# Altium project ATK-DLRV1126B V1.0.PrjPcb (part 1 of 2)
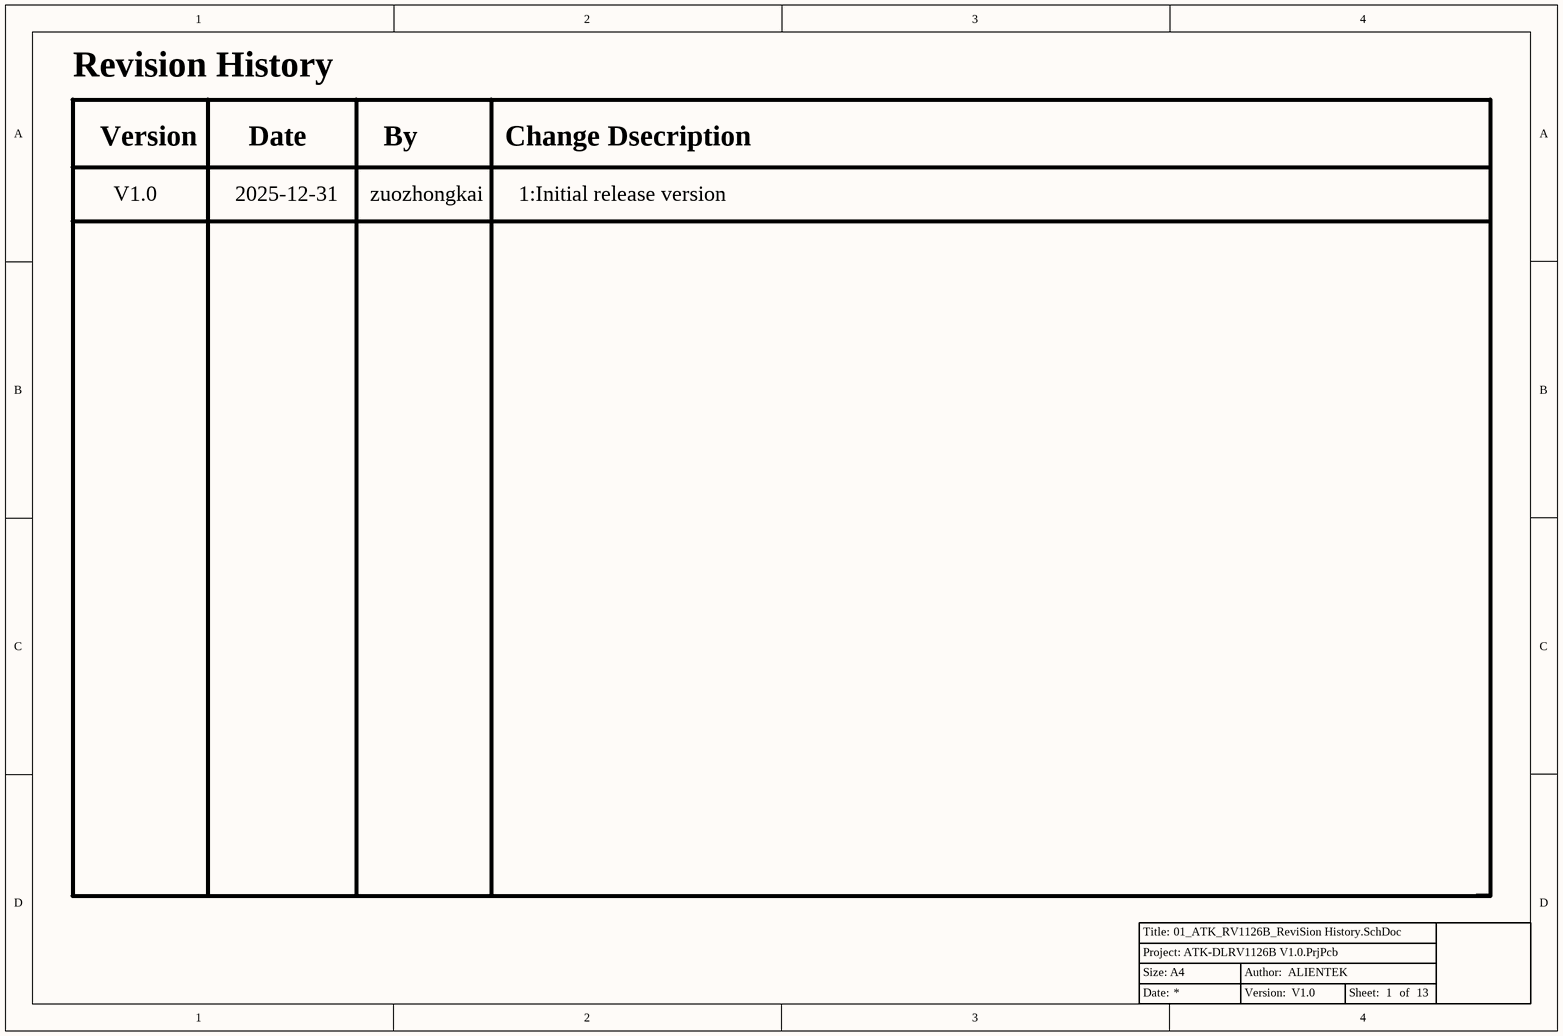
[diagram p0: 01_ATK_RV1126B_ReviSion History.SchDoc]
13 sheets, 503 parts. Net scope: global (net labels, ports and power ports of the same name join across sheets).
Sheets:
  01_ATK_RV1126B_ReviSion History.SchDoc
  02_ATK_RV1126B_Core_Board.SchDoc
  03_ATK_RV1126B_Power_USB.SchDoc
  04_ATK_RV1126B_4G_USBHUB.SchDoc
  05_ATK_RV1126B_DEVICE.SchDoc
  06_ATK_RV1126B_ES8390_Audio.SchDoc
  07_ATK_RV1126B_Integrate_Audio_OPT.SchDoc
  08_ATK_RV1126B_RS485_CAN.SchDoc
  09_ATK_RV1126B_RGMII_NET.SchDoc
  10_ATK_RV1126B_FEPHY_NET_OPT.SchDoc
  11_ATK_RV1126B_TYPEC_USB30.SchDoc
  12_ATK_RV1126B_CSI_DSI.SchDoc
  13_ATK_RV1126B_WIFI_CIF_PIN.SchDoc

## Sheet 01_ATK_RV1126B_ReviSion History.SchDoc
size A4; Author: ALIENTEK; SheetNumber: 1; SheetTotal: 13; SheetSize: A4; Version: V1.0

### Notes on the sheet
- Revision History
- Version
- Date
- By
- Change Dsecription
- V1.0
- 2025-12-31
- zuozhongkai
- 1:Initial release version

## Sheet 02_ATK_RV1126B_Core_Board.SchDoc
size A3; Date: 13; Author: ALIENTEK; Revision: 0; SheetNumber: 2; SheetTotal: 13; Version: V1.0; SheetSize: A3
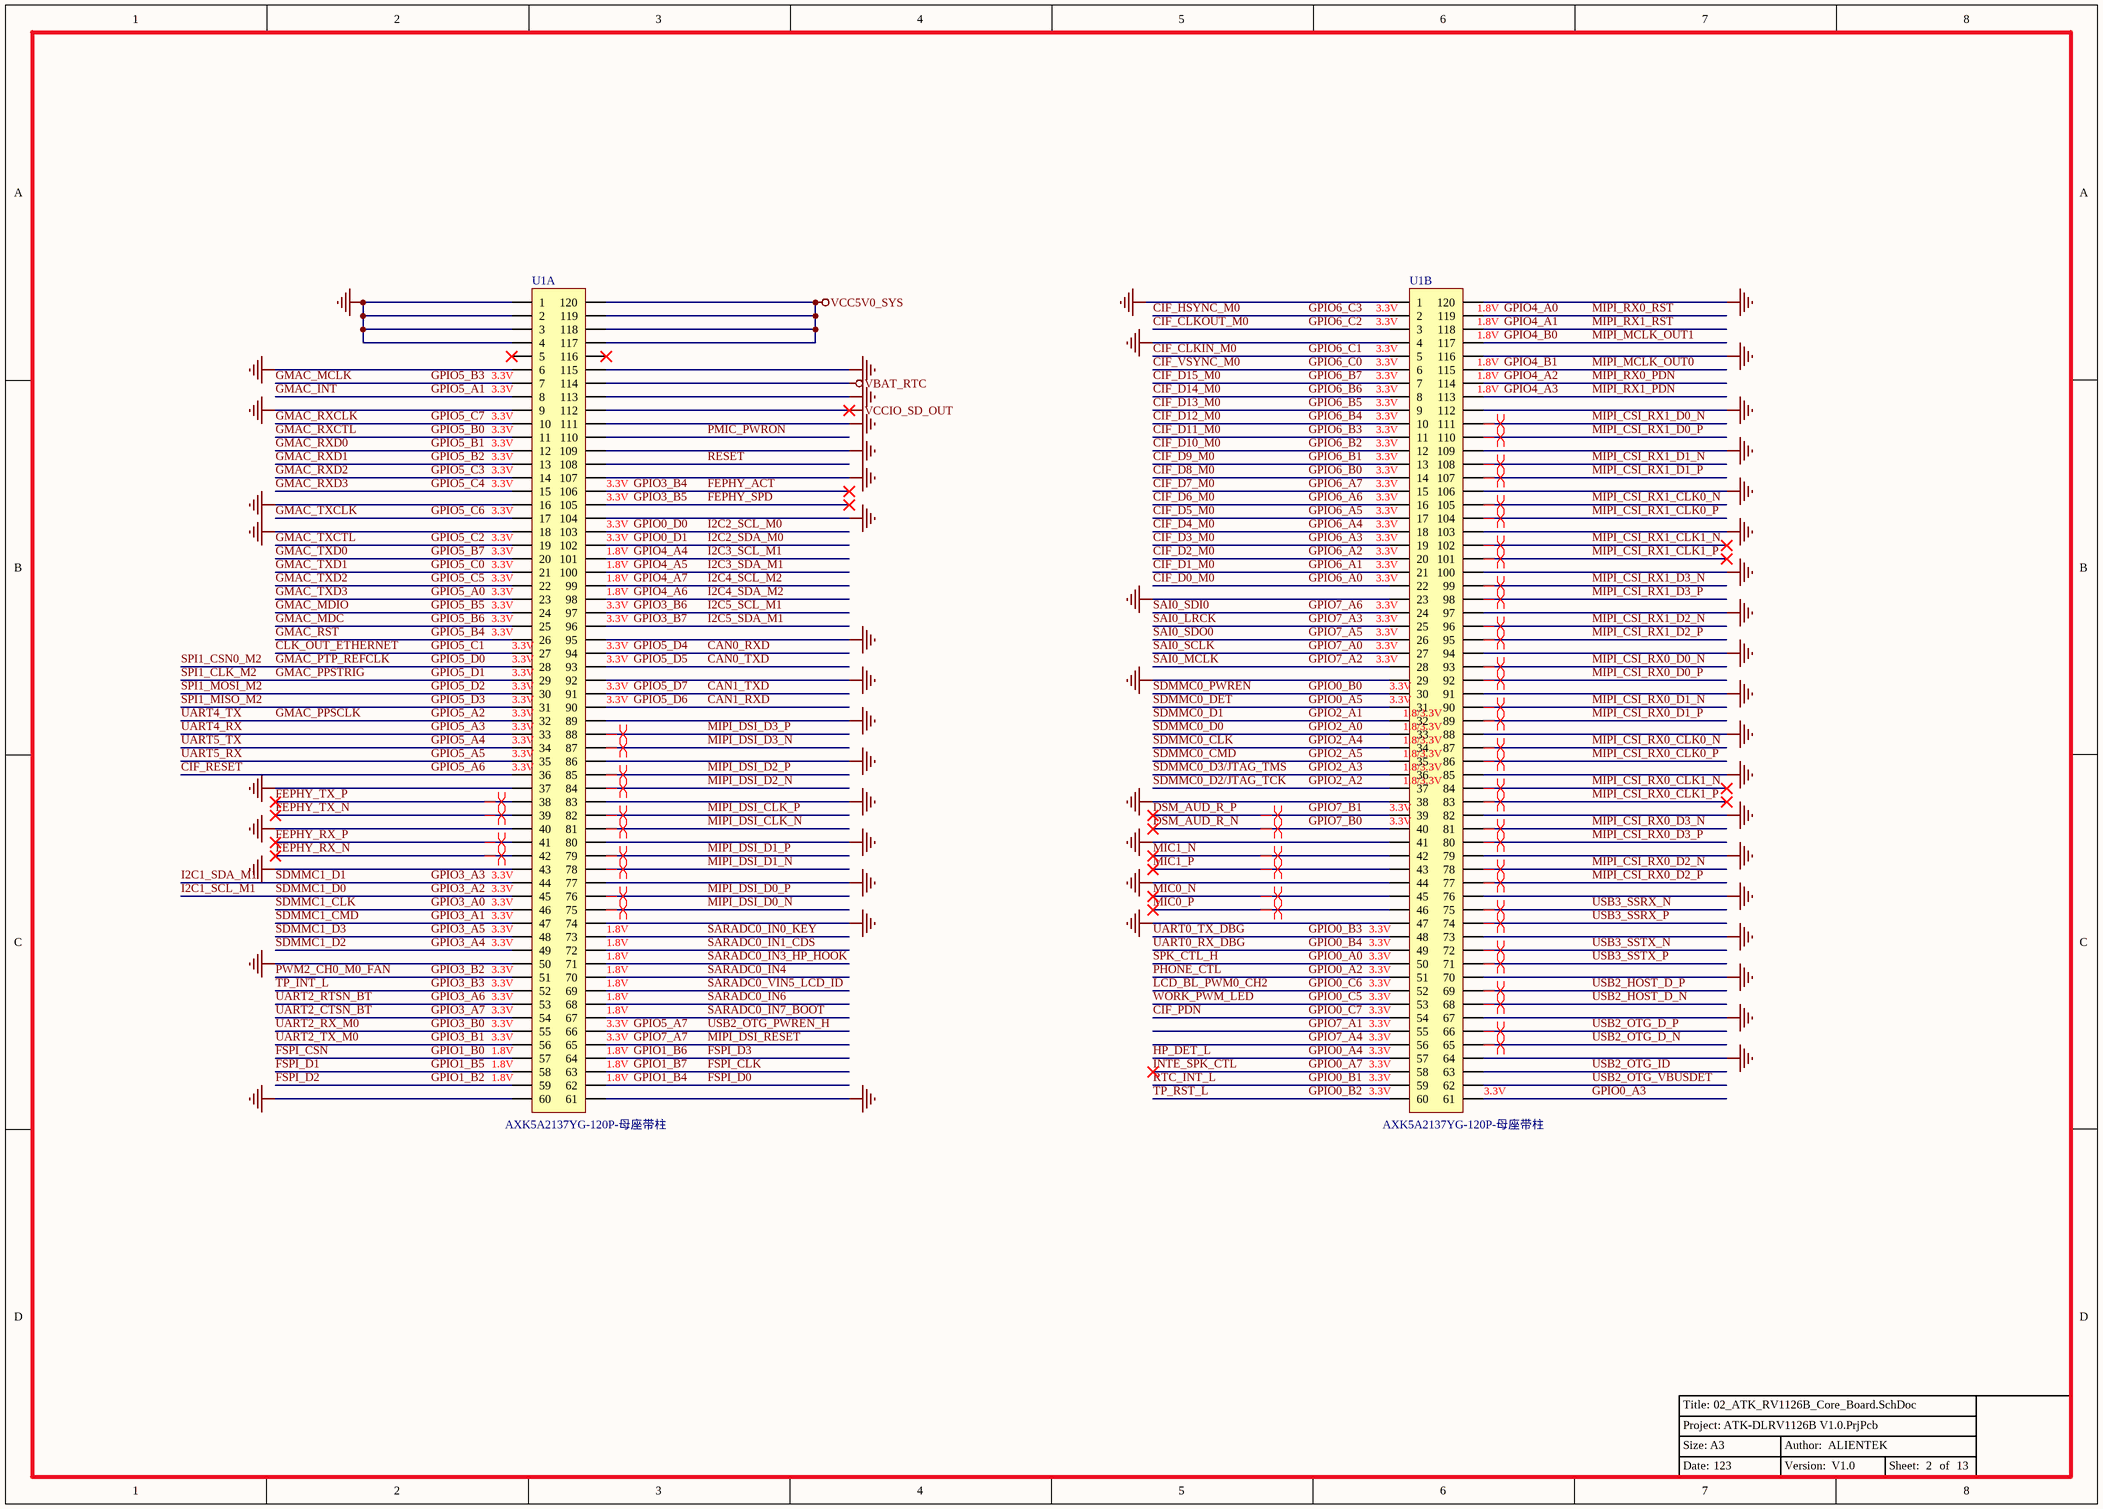
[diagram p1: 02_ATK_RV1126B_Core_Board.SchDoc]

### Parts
U1  AXK5A2137YG-120P-母座带柱  [ATK-CLRV1126B-CORE]  (parts A,B of 2)

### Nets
GND: U1.A1(1) U1.A2(2) U1.A3(3) U1.A4(4) U1.A6(6) U1.A9(9) U1.A16(16) U1.A18(18) U1.A37(37) U1.A40(40) U1.A43(43) U1.A50(50) U1.A60(60) U1.A61(61) U1.A74(74) U1.A77(77) U1.A80(80) U1.A83(83) U1.A86(86) U1.A89(89) U1.A92(92) U1.A95(95) U1.A104(104) U1.A107(107) U1.A109(109) U1.A111(111) U1.A113(113) U1.A115(115) U1.B1(1) U1.B4(4) U1.B23(23) U1.B29(29) U1.B38(38) U1.B41(41) U1.B44(44) U1.B47(47) U1.B64(64) U1.B67(67) U1.B70(70) U1.B73(73) U1.B76(76) U1.B79(79) U1.B82(82) U1.B85(85) U1.B88(88) U1.B91(91) U1.B94(94) U1.B97(97) U1.B100(100) U1.B103(103) U1.B106(106) U1.B109(109) U1.B112(112) U1.B116(116) U1.B120(120)
VBAT_RTC: U1.A114(114)
VCC5V0_SYS: U1.A117(117) U1.A118(118) U1.A119(119) U1.A120(120)
VCCIO_SD_OUT: U1.A112(112)
CAN0_RXD: U1.A94(94)  [also labelled GPIO5_D4]
CAN0_TXD: U1.A93(93)  [also labelled GPIO5_D5]
CAN1_RXD: U1.A90(90)  [also labelled GPIO5_D6]
CAN1_TXD: U1.A91(91)  [also labelled GPIO5_D7]
CIF_CLKIN_M0: U1.B5(5)  [also labelled GPIO6_C1]
CIF_CLKOUT_M0: U1.B3(3)  [also labelled GPIO6_C2]
CIF_D0_M0: U1.B22(22)  [also labelled GPIO6_A0]
CIF_D1_M0: U1.B21(21)  [also labelled GPIO6_A1]
CIF_D2_M0: U1.B20(20)  [also labelled GPIO6_A2]
CIF_D3_M0: U1.B19(19)  [also labelled GPIO6_A3]
CIF_D4_M0: U1.B18(18)  [also labelled GPIO6_A4]
CIF_D5_M0: U1.B17(17)  [also labelled GPIO6_A5]
CIF_D6_M0: U1.B16(16)  [also labelled GPIO6_A6]
CIF_D7_M0: U1.B15(15)  [also labelled GPIO6_A7]
CIF_D8_M0: U1.B14(14)  [also labelled GPIO6_B0]
CIF_D9_M0: U1.B13(13)  [also labelled GPIO6_B1]
CIF_D10_M0: U1.B12(12)  [also labelled GPIO6_B2]
CIF_D11_M0: U1.B11(11)  [also labelled GPIO6_B3]
CIF_D12_M0: U1.B10(10)  [also labelled GPIO6_B4]
CIF_D13_M0: U1.B9(9)  [also labelled GPIO6_B5]
CIF_D14_M0: U1.B8(8)  [also labelled GPIO6_B6]
CIF_D15_M0: U1.B7(7)  [also labelled GPIO6_B7]
CIF_HSYNC_M0: U1.B2(2)  [also labelled GPIO6_C3]
CIF_PDN: U1.B54(54)  [also labelled GPIO0_C7]
CIF_RESET: U1.A36(36)  [also labelled GPIO5_A6]
CIF_VSYNC_M0: U1.B6(6)  [also labelled GPIO6_C0]
CLK_OUT_ETHERNET: U1.A27(27)  [also labelled GPIO5_C1]
DSM_AUD_R_N: U1.B40(40)  [also labelled GPIO7_B0]
DSM_AUD_R_P: U1.B39(39)  [also labelled GPIO7_B1]
FEPHY_ACT: U1.A106(106)  [also labelled GPIO3_B4]
FEPHY_RX_N: U1.A42(42)
FEPHY_RX_P: U1.A41(41)
FEPHY_SPD: U1.A105(105)  [also labelled GPIO3_B5]
FEPHY_TX_N: U1.A39(39)
FEPHY_TX_P: U1.A38(38)
FSPI_CLK: U1.A63(63)  [also labelled GPIO1_B7]
FSPI_CSN: U1.A57(57)  [also labelled GPIO1_B0]
FSPI_D0: U1.A62(62)  [also labelled GPIO1_B4]
FSPI_D1: U1.A58(58)  [also labelled GPIO1_B5]
FSPI_D2: U1.A59(59)  [also labelled GPIO1_B2]
FSPI_D3: U1.A64(64)  [also labelled GPIO1_B6]
GMAC_INT: U1.A8(8)  [also labelled GPIO5_A1]
GMAC_MCLK: U1.A7(7)  [also labelled GPIO5_B3]
GMAC_MDC: U1.A25(25)  [also labelled GPIO5_B6]
GMAC_MDIO: U1.A24(24)  [also labelled GPIO5_B5]
GMAC_PPSCLK: U1.A32(32)  [also labelled GPIO5_A2, UART4_TX]
GMAC_PPSTRIG: U1.A29(29)  [also labelled GPIO5_D1, SPI1_CLK_M2]
GMAC_PTP_REFCLK: U1.A28(28)  [also labelled GPIO5_D0, SPI1_CSN0_M2]
GMAC_RST: U1.A26(26)  [also labelled GPIO5_B4]
GMAC_RXCLK: U1.A10(10)  [also labelled GPIO5_C7]
GMAC_RXCTL: U1.A11(11)  [also labelled GPIO5_B0]
GMAC_RXD0: U1.A12(12)  [also labelled GPIO5_B1]
GMAC_RXD1: U1.A13(13)  [also labelled GPIO5_B2]
GMAC_RXD2: U1.A14(14)  [also labelled GPIO5_C3]
GMAC_RXD3: U1.A15(15)  [also labelled GPIO5_C4]
GMAC_TXCLK: U1.A17(17)  [also labelled GPIO5_C6]
GMAC_TXCTL: U1.A19(19)  [also labelled GPIO5_C2]
GMAC_TXD0: U1.A20(20)  [also labelled GPIO5_B7]
GMAC_TXD1: U1.A21(21)  [also labelled GPIO5_C0]
GMAC_TXD2: U1.A22(22)  [also labelled GPIO5_C5]
GMAC_TXD3: U1.A23(23)  [also labelled GPIO5_A0]
GPIO0_A0: U1.B50(50)  [also labelled SPK_CTL_H]
GPIO0_A2: U1.B51(51)  [also labelled PHONE_CTL]
GPIO0_A3: U1.B61(61)
GPIO0_A4: U1.B57(57)  [also labelled HP_DET_L]
GPIO0_A5: U1.B31(31)  [also labelled SDMMC0_DET]
GPIO0_A7: U1.B58(58)  [also labelled INTE_SPK_CTL]
GPIO0_B0: U1.B30(30)  [also labelled SDMMC0_PWREN]
GPIO0_B1: U1.B59(59)  [also labelled RTC_INT_L]
GPIO0_B2: U1.B60(60)  [also labelled TP_RST_L]
GPIO0_B3: U1.B48(48)  [also labelled UART0_TX_DBG]
GPIO0_B4: U1.B49(49)  [also labelled UART0_RX_DBG]
GPIO0_C5: U1.B53(53)  [also labelled WORK_PWM_LED]
GPIO0_C6: U1.B52(52)  [also labelled LCD_BL_PWM0_CH2]
GPIO0_D0: U1.A103(103)  [also labelled I2C2_SCL_M0]
GPIO0_D1: U1.A102(102)  [also labelled I2C2_SDA_M0]
GPIO2_A0: U1.B33(33)  [also labelled SDMMC0_D0]
GPIO2_A1: U1.B32(32)  [also labelled SDMMC0_D1]
GPIO2_A2: U1.B37(37)  [also labelled SDMMC0_D2/JTAG_TCK]
GPIO2_A3: U1.B36(36)  [also labelled SDMMC0_D3/JTAG_TMS]
GPIO2_A4: U1.B34(34)  [also labelled SDMMC0_CLK]
GPIO2_A5: U1.B35(35)  [also labelled SDMMC0_CMD]
GPIO3_A0: U1.A46(46)  [also labelled SDMMC1_CLK]
GPIO3_A1: U1.A47(47)  [also labelled SDMMC1_CMD]
GPIO3_A2: U1.A45(45)  [also labelled I2C1_SCL_M1, SDMMC1_D0]
GPIO3_A3: U1.A44(44)  [also labelled I2C1_SDA_M1, SDMMC1_D1]
GPIO3_A4: U1.A49(49)  [also labelled SDMMC1_D2]
GPIO3_A5: U1.A48(48)  [also labelled SDMMC1_D3]
GPIO3_A6: U1.A53(53)  [also labelled UART2_RTSN_BT]
GPIO3_A7: U1.A54(54)  [also labelled UART2_CTSN_BT]
GPIO3_B0: U1.A55(55)  [also labelled UART2_RX_M0]
GPIO3_B1: U1.A56(56)  [also labelled UART2_TX_M0]
GPIO3_B2: U1.A51(51)  [also labelled PWM2_CH0_M0_FAN]
GPIO3_B3: U1.A52(52)  [also labelled TP_INT_L]
GPIO3_B6: U1.A97(97)  [also labelled I2C5_SCL_M1]
GPIO3_B7: U1.A96(96)  [also labelled I2C5_SDA_M1]
GPIO4_A0: U1.B119(119)  [also labelled MIPI_RX0_RST]
GPIO4_A1: U1.B118(118)  [also labelled MIPI_RX1_RST]
GPIO4_A2: U1.B114(114)  [also labelled MIPI_RX0_PDN]
GPIO4_A3: U1.B113(113)  [also labelled MIPI_RX1_PDN]
GPIO4_A4: U1.A101(101)  [also labelled I2C3_SCL_M1]
GPIO4_A5: U1.A100(100)  [also labelled I2C3_SDA_M1]
GPIO4_A6: U1.A98(98)  [also labelled I2C4_SDA_M2]
GPIO4_A7: U1.A99(99)  [also labelled I2C4_SCL_M2]
GPIO4_B0: U1.B117(117)  [also labelled MIPI_MCLK_OUT1]
GPIO4_B1: U1.B115(115)  [also labelled MIPI_MCLK_OUT0]
GPIO5_A3: U1.A33(33)  [also labelled UART4_RX]
GPIO5_A4: U1.A34(34)  [also labelled UART5_TX]
GPIO5_A5: U1.A35(35)  [also labelled UART5_RX]
GPIO5_A7: U1.A66(66)  [also labelled USB2_OTG_PWREN_H]
GPIO5_D2: U1.A30(30)  [also labelled SPI1_MOSI_M2]
GPIO5_D3: U1.A31(31)  [also labelled SPI1_MISO_M2]
GPIO7_A0: U1.B27(27)  [also labelled SAI0_SCLK]
GPIO7_A1: U1.B55(55)
GPIO7_A2: U1.B28(28)  [also labelled SAI0_MCLK]
GPIO7_A3: U1.B25(25)  [also labelled SAI0_LRCK]
GPIO7_A4: U1.B56(56)
GPIO7_A5: U1.B26(26)  [also labelled SAI0_SDO0]
GPIO7_A6: U1.B24(24)  [also labelled SAI0_SDI0]
GPIO7_A7: U1.A65(65)  [also labelled MIPI_DSI_RESET]
MIC0_N: U1.B45(45)
MIC0_P: U1.B46(46)
MIC1_N: U1.B42(42)
MIC1_P: U1.B43(43)
MIPI_CSI_RX0_CLK0_N: U1.B87(87)
MIPI_CSI_RX0_CLK0_P: U1.B86(86)
MIPI_CSI_RX0_CLK1_N: U1.B84(84)
MIPI_CSI_RX0_CLK1_P: U1.B83(83)
MIPI_CSI_RX0_D0_N: U1.B93(93)
MIPI_CSI_RX0_D0_P: U1.B92(92)
MIPI_CSI_RX0_D1_N: U1.B90(90)
MIPI_CSI_RX0_D1_P: U1.B89(89)
MIPI_CSI_RX0_D2_N: U1.B78(78)
MIPI_CSI_RX0_D2_P: U1.B77(77)
MIPI_CSI_RX0_D3_N: U1.B81(81)
MIPI_CSI_RX0_D3_P: U1.B80(80)
MIPI_CSI_RX1_CLK0_N: U1.B105(105)
MIPI_CSI_RX1_CLK0_P: U1.B104(104)
MIPI_CSI_RX1_CLK1_N: U1.B102(102)
MIPI_CSI_RX1_CLK1_P: U1.B101(101)
MIPI_CSI_RX1_D0_N: U1.B111(111)
MIPI_CSI_RX1_D0_P: U1.B110(110)
MIPI_CSI_RX1_D1_N: U1.B108(108)
MIPI_CSI_RX1_D1_P: U1.B107(107)
MIPI_CSI_RX1_D2_N: U1.B96(96)
MIPI_CSI_RX1_D2_P: U1.B95(95)
MIPI_CSI_RX1_D3_N: U1.B99(99)
MIPI_CSI_RX1_D3_P: U1.B98(98)
MIPI_DSI_CLK_N: U1.A81(81)
MIPI_DSI_CLK_P: U1.A82(82)
MIPI_DSI_D0_N: U1.A75(75)
MIPI_DSI_D0_P: U1.A76(76)
MIPI_DSI_D1_N: U1.A78(78)
MIPI_DSI_D1_P: U1.A79(79)
MIPI_DSI_D2_N: U1.A84(84)
MIPI_DSI_D2_P: U1.A85(85)
MIPI_DSI_D3_N: U1.A87(87)
MIPI_DSI_D3_P: U1.A88(88)
PMIC_PWRON: U1.A110(110)
RESET: U1.A108(108)
SARADC0_IN0_KEY: U1.A73(73)
SARADC0_IN1_CDS: U1.A72(72)
SARADC0_IN3_HP_HOOK: U1.A71(71)
SARADC0_IN4: U1.A70(70)
SARADC0_IN6: U1.A68(68)
SARADC0_IN7_BOOT: U1.A67(67)
SARADC0_VIN5_LCD_ID: U1.A69(69)
USB2_HOST_D_N: U1.B68(68)
USB2_HOST_D_P: U1.B69(69)
USB2_OTG_D_N: U1.B65(65)
USB2_OTG_D_P: U1.B66(66)
USB2_OTG_ID: U1.B63(63)
USB2_OTG_VBUSDET: U1.B62(62)
USB3_SSRX_N: U1.B75(75)
USB3_SSRX_P: U1.B74(74)
USB3_SSTX_N: U1.B72(72)
USB3_SSTX_P: U1.B71(71)

Not connected (* = marked no-connect by the designer): U1 A5(5)* A116(116)*

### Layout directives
differential pair: DSM_AUD_R_N, DSM_AUD_R_P, FEPHY_RX_N, FEPHY_RX_P, FEPHY_TX_N, FEPHY_TX_P, MIC0_N, MIC0_P, MIC1_N, MIC1_P, MIPI_CSI_RX0_CLK0_N, MIPI_CSI_RX0_CLK0_P, MIPI_CSI_RX0_CLK1_N, MIPI_CSI_RX0_CLK1_P, MIPI_CSI_RX0_D0_N, MIPI_CSI_RX0_D0_P, MIPI_CSI_RX0_D1_N, MIPI_CSI_RX0_D1_P, MIPI_CSI_RX0_D2_N, MIPI_CSI_RX0_D2_P, MIPI_CSI_RX0_D3_N, MIPI_CSI_RX0_D3_P, MIPI_CSI_RX1_CLK0_N, MIPI_CSI_RX1_CLK0_P, MIPI_CSI_RX1_CLK1_N, MIPI_CSI_RX1_CLK1_P, MIPI_CSI_RX1_D0_N, MIPI_CSI_RX1_D0_P, MIPI_CSI_RX1_D1_N, MIPI_CSI_RX1_D1_P, MIPI_CSI_RX1_D2_N, MIPI_CSI_RX1_D2_P, MIPI_CSI_RX1_D3_N, MIPI_CSI_RX1_D3_P, MIPI_DSI_CLK_N, MIPI_DSI_CLK_P, MIPI_DSI_D0_N, MIPI_DSI_D0_P, MIPI_DSI_D1_N, MIPI_DSI_D1_P, MIPI_DSI_D2_N, MIPI_DSI_D2_P, MIPI_DSI_D3_N, MIPI_DSI_D3_P, USB2_HOST_D_N, USB2_HOST_D_P, USB2_OTG_D_N, USB2_OTG_D_P, USB3_SSRX_N, USB3_SSRX_P, USB3_SSTX_N, USB3_SSTX_P

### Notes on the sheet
- (near U1) 3.3V
- (near U1) 1.8V
- (near U1) 1.8/3.3V

## Sheet 03_ATK_RV1126B_Power_USB.SchDoc
size A3; Date: 13; Author: ALIENTEK; Revision: 0; SheetNumber: 3; SheetTotal: 13; Version: V1.0; SheetSize: A3
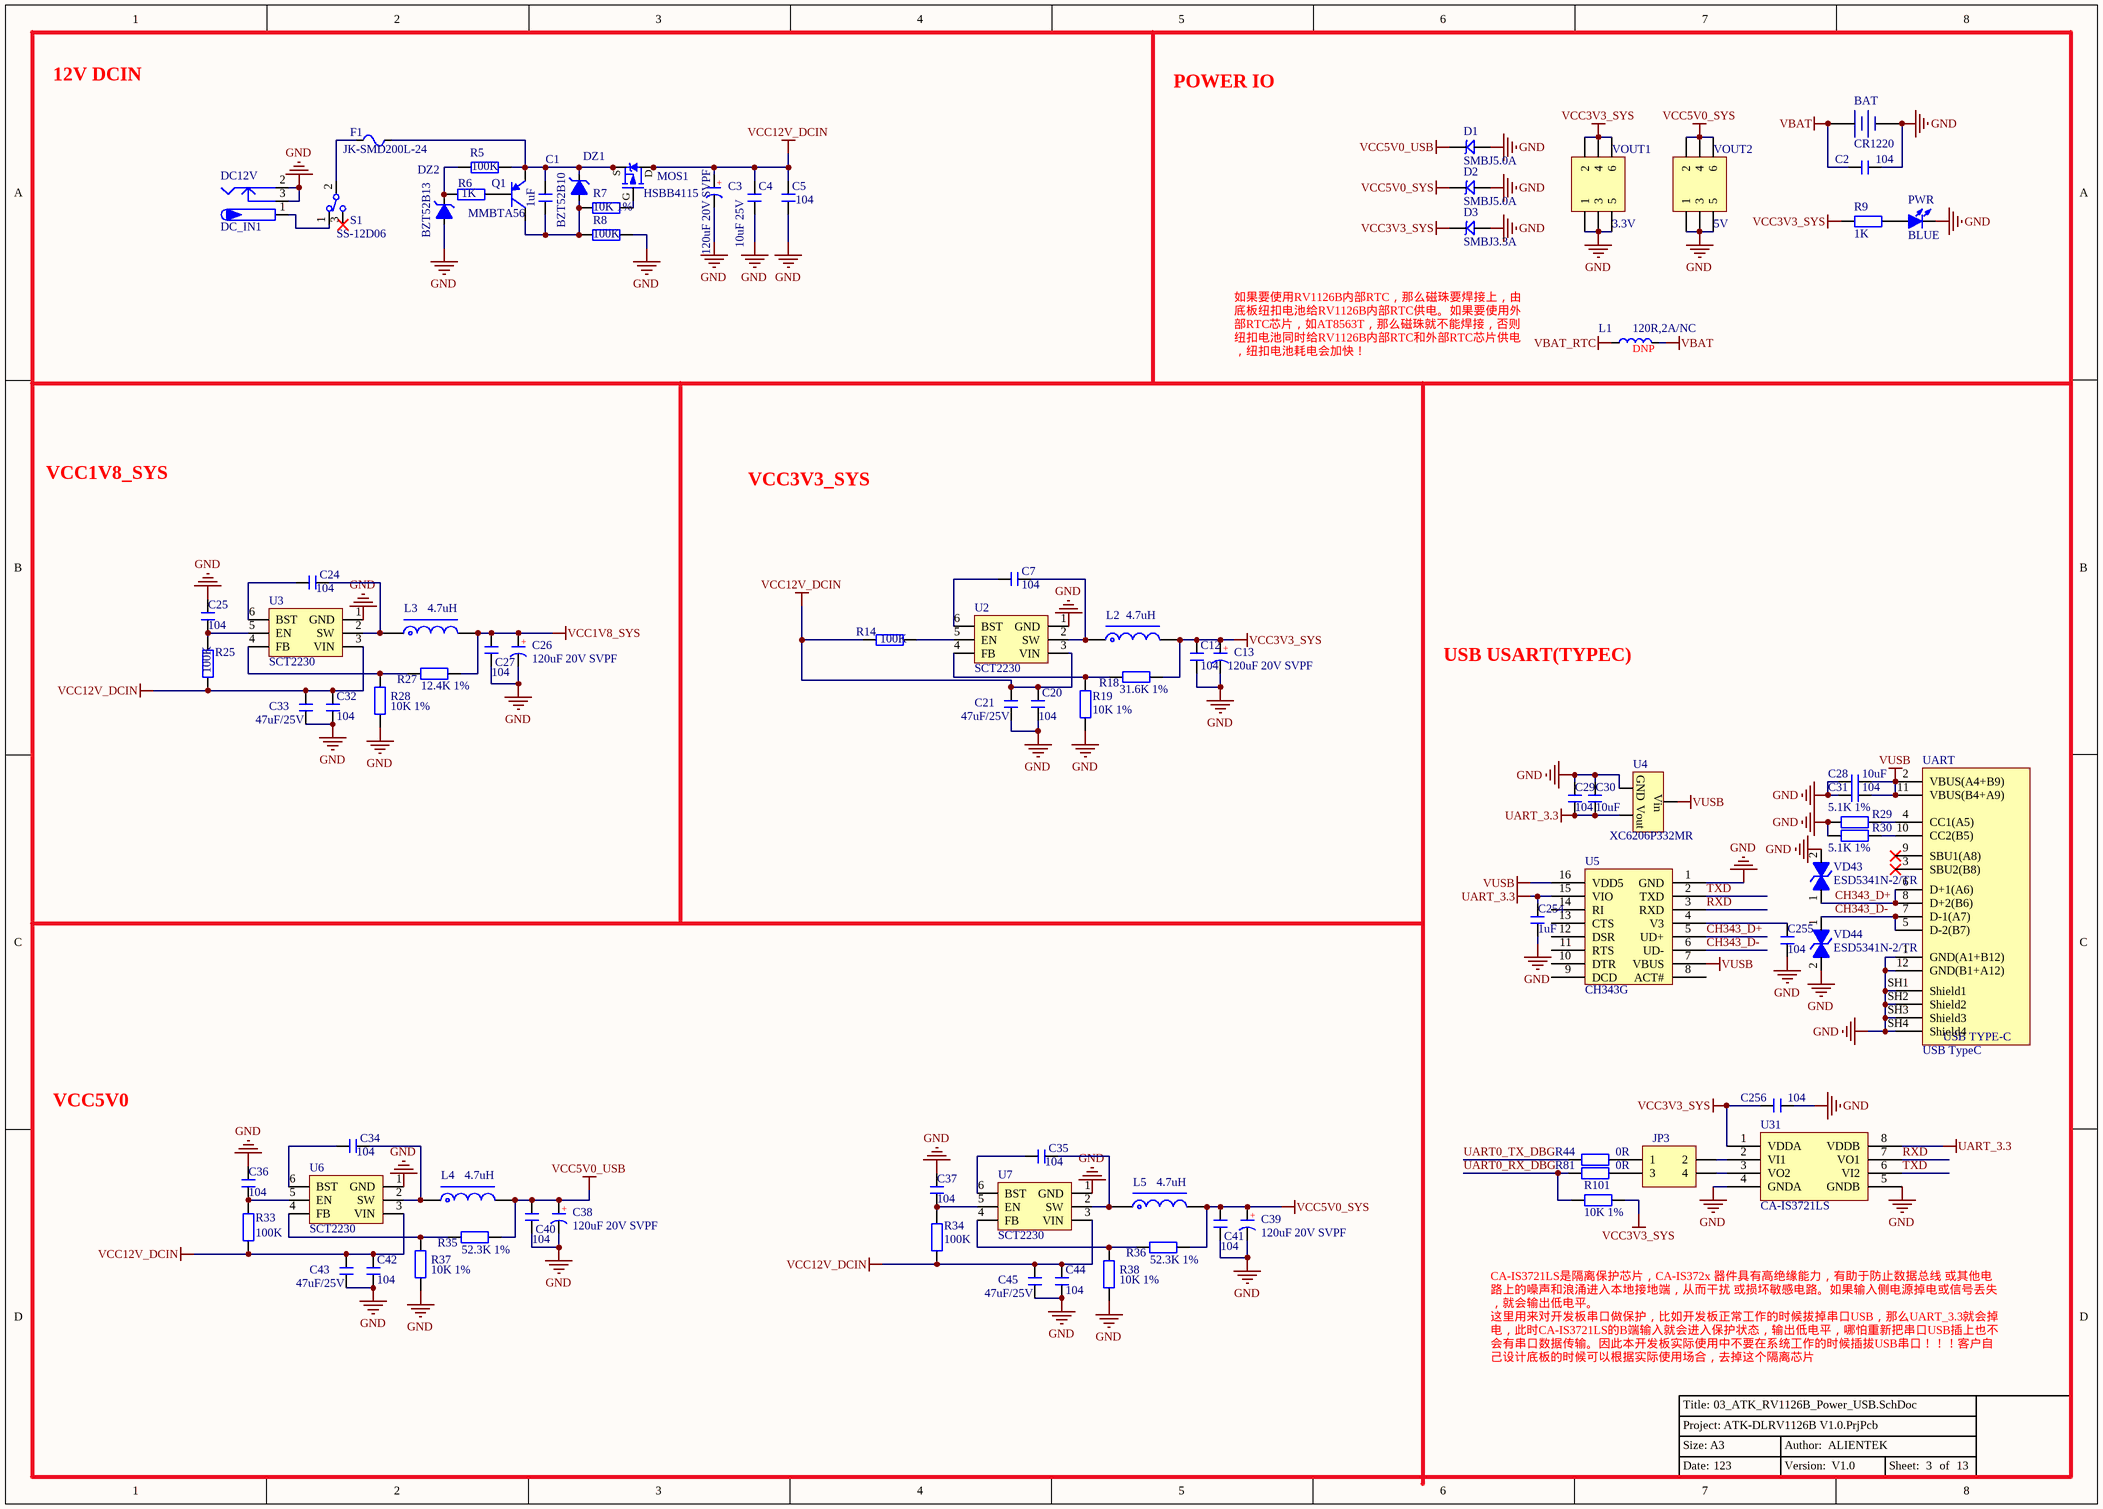
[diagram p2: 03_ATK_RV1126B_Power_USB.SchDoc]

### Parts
3.3V  VOUT1  [HDR-3X2]
5V  VOUT2  [HDR-3X2]
BAT  CR1220  [CR1220_A]
C1  1uF  [C 0603]
C2  104  [C 0402]
C3  120uF 20V SVPF  [CM D(6.3*7.7)]
C4  10uF 25V  [C 1206]
C5  104  [C 0402]
C7  104  [C 0402]
C12  104  [C 0402]
C13  120uF 20V SVPF  [CM D(6.3*7.7)]
C20  104  [C 0402]
C21  47uF/25V  [C 1206]
C24  104  [C 0402]
C25  104  [C 0402]
C26  120uF 20V SVPF  [CM D(6.3*7.7)]
C27  104  [C 0402]
C28  10uF  [C 0603]
C29  104  [C 0402]
C30  10uF  [C 0603]
C31  104  [C 0402]
C32  104  [C 0402]
C33  47uF/25V  [C 1206]
C34  104  [C 0402]
C35  104  [C 0402]
C36  104  [C 0402]
C37  104  [C 0402]
C38  120uF 20V SVPF  [CM D(6.3*7.7)]
C39  120uF 20V SVPF  [CM D(6.3*7.7)]
C40  104  [C 0402]
C41  104  [C 0402]
C42  104  [C 0402]
C43  47uF/25V  [C 1206]
C44  104  [C 0402]
C45  47uF/25V  [C 1206]
C254  1uF  [C 0402]
C255  104  [C 0402]
C256  104  [C 0402]
D1  SMBJ5.0A  [SMBJ]
D2  SMBJ5.0A  [SMBJ]
D3  SMBJ3.3A  [SMBJ]
DC12V  DC_IN1  [DC10B]
DZ1  BZT52B10  [SOD-123]
DZ2  BZT52B13  [SOD-123]
F1  JK-SMD200L-24  [FU 1812]
JP3  Header2X2  [HDR-2X2]  (value not drawn)
L1  120R,2A/NC  [L 0603]
L2  4.7uH  [L-SMD-0420]
L3  4.7uH  [L-SMD-0420]
L4  4.7uH  [L-SMD-0420]
L5  4.7uH  [L-SMD-0420]
MOS1  HSBB4115  [DFN8_ 3x3]
PWR  BLUE  [LED 0805B]
Q1  MMBTA56  [SOT23-3N]
R5  100K  [R 0402]
R6  1K  [R 0402]
R7  10K 1%  [R 0402]
R8  100K  [R 0402]
R9  1K  [R 0402]
R14  100K  [R 0402]
R18  31.6K 1%  [R 0402]
R19  10K 1%  [R 0402]
R25  100K  [R 0402]
R27  12.4K 1%  [R 0402]
R28  10K 1%  [R 0402]
R29  5.1K 1%  [R 0402]
R30  5.1K 1%  [R 0402]
R33  100K  [R 0402]
R34  100K  [R 0402]
R35  52.3K 1%  [R 0402]
R36  52.3K 1%  [R 0402]
R37  10K 1%  [R 0402]
R38  10K 1%  [R 0402]
R44  0R  [R 0402]
R81  0R  [R 0402]
R101  10K 1%  [R 0402]
S1  SS-12D06  [SS-12D06]
U2  SCT2230  [SOT23-6N]
U3  SCT2230  [SOT23-6N]
U4  XC6206P332MR  [SOT23-3L]
U5  CH343G  [SOP16_M]
U6  SCT2230  [SOT23-6N]
U7  SCT2230  [SOT23-6N]
U31  CA-IS3721LS  [SOIC-8 6.2*5.1]
UART  USB TypeC  [USB2.0-TYPE-C-16P]
VD43  ESD5341N-2/TR  [ESD0402]
VD44  ESD5341N-2/TR  [ESD0402]

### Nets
GND: 3.3V.1 3.3V.3 3.3V.5 5V.1 5V.3 5V.5 BAT.2(DC-) C2.2 C3.2(K) C4.2 C5.2 C12.2 C13.2(K) C20.1 C21.1 C25.2 C26.2(K) C27.2 C28.2 C29.2 C30.2 C31.2 C32.1 C33.1 C36.2 C37.2 C38.2(K) C39.2(K) C40.2 C41.2 C42.1 C43.1 C44.1 C45.1 C254.1 C255.1 C256.1 D1.1 D2.1 D3.1 DC12V.2 DC12V.3 DZ2.1(A) PWR.2(K) R8.2 R19.2 R28.2 R29.1 R30.1 R37.2 R38.2 U2.1(GND) U3.1(GND) U4.1(GND) U5.1(GND) U6.1(GND) U7.1(GND) U31.4(GNDA) U31.5(GNDB) UART.1(GND(A1+B12)) UART.12(GND(B1+A12)) UART.SH1(Shield1) UART.SH2(Shield2) UART.SH3(Shield3) UART.SH4(Shield4) VD43.2 VD44.2
UART_3.3: C29.1 C30.1 C254.2 U4.2(Vout) U5.15(VIO) U31.8(VDDB)
VBAT: BAT.1(DC+) C2.1 L1.2
VBAT_RTC: L1.1
VCC1V8_SYS: C26.1(A) C27.1 L3.2 R27.2
VCC3V3_SYS: 3.3V.2 3.3V.4 3.3V.6 C12.1 C13.1(A) C256.2 D3.2 L2.2 R9.2 R18.2 R101.2 U31.1(VDDA)
VCC5V0_SYS: 5V.2 5V.4 5V.6 C39.1(A) C41.1 D2.2 L5.2 R36.2
VCC5V0_USB: C38.1(A) C40.1 D1.2 L4.2 R35.2
VCC12V_DCIN: C3.1(A) C4.1 C5.1 C20.2 C21.2 C32.2 C33.2 C42.2 C43.2 C44.2 C45.2 MOS1.5(D) MOS1.6(D) MOS1.7(D) MOS1.8(D) R14.1 R25.2 R33.2 R34.2 U2.3(VIN) U3.3(VIN) U6.3(VIN) U7.3(VIN)
VUSB: C28.1 C31.1 U4.3(Vin) U5.7(VBUS) U5.16(VDD5) UART.2(VBUS(A4+B9)) UART.11(VBUS(B4+A9))
CH343_D+: U5.5(UD+) UART.6(D+1(A6)) UART.8(D+2(B6)) VD43.1
CH343_D-: U5.6(UD-) UART.5(D-2(B7)) UART.7(D-1(A7)) VD44.1
RXD: U5.3(RXD) U31.7(VO1)
TXD: U5.2(TXD) U31.6(VI2)
UART0_RX_DBG: R81.2 R101.1  [project net GPIO0_B4]
UART0_TX_DBG: R44.2  [project net GPIO0_B3]
NetC1_1: C1.1 DZ1.2(K) F1.1 MOS1.1(S) MOS1.2(S) MOS1.3(G) Q1.2(E) R5.1
NetC1_2: C1.2 DZ1.1(A) Q1.3(C) R7.1 R8.1
NetC7_1: C7.1 U2.6(BST)
NetC7_2: C7.2 L2.1 U2.2(SW)
NetC24_1: C24.1 U3.6(BST)
NetC24_2: C24.2 L3.1 U3.2(SW)
NetC25_1: C25.1 R25.1 U3.5(EN)
NetC34_1: C34.1 U6.6(BST)
NetC34_2: C34.2 L4.1 U6.2(SW)
NetC35_1: C35.1 U7.6(BST)
NetC35_2: C35.2 L5.1 U7.2(SW)
NetC36_1: C36.1 R33.1 U6.5(EN)
NetC37_1: C37.1 R34.1 U7.5(EN)
NetC255_2: C255.2 U5.4(V3)
NetDC12V_1: DC12V.1 S1.1
NetDZ2_2: DZ2.2(K) R5.2 R6.1
NetF1_2: F1.2 S1.2
NetJP3_1: JP3.1 R44.1
NetJP3_2: JP3.2 U31.2(VI1)
NetJP3_3: JP3.3 R81.1
NetJP3_4: JP3.4 U31.3(VO2)
NetMOS1_4: MOS1.4(G) R7.2
NetPWR_1: PWR.1(A) R9.1
NetQ1_1: Q1.1(B) R6.2
NetR14_2: R14.2 U2.5(EN)
NetR18_1: R18.1 R19.1 U2.4(FB)
NetR27_1: R27.1 R28.1 U3.4(FB)
NetR29_2: R29.2 UART.4(CC1(A5))
NetR30_2: R30.2 UART.10(CC2(B5))
NetR35_1: R35.1 R37.1 U6.4(FB)
NetR36_1: R36.1 R38.1 U7.4(FB)

Not connected (* = marked no-connect by the designer): S1 3*; U5 8(ACT#) 9(DCD) 10(DTR) 11(RTS) 12(DSR) 13(CTS) 14(RI); UART 3(SBU2(B8))* 9(SBU1(A8))*

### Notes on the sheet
- 12V DCIN
- POWER IO
- 如果要使用RV1126B内部RTC，那么磁珠要焊接上，由底板纽扣电池给RV1126B内部RTC供电。如果要使用外部RTC芯片，如AT8563T，那么磁珠就不能焊接，否则纽扣电池同时给RV1126B内部RTC和外部RTC芯片供电，纽扣电池耗电会加快！
- (near L1) DNP
- VCC1V8_SYS
- VCC3V3_SYS
- USB USART(TYPEC)
- VCC5V0
- CA-IS3721LS是隔离保护芯片，CA-IS372x 器件具有高绝缘能力，有助于防止数据总线 或其他电路上的噪声和浪涌进入本地接地端，从而干扰 或损坏敏感电路。如果输入侧电源掉电或信号丢失，就会输出低电平。
  这里用来对开发板串口做保护，比如开发板正常工作的时候拔掉串口USB，那么UART_3.3就会掉电，此时CA-IS3721LS的B端输入就会进入保护状态，输出低电平，哪怕重新把串口USB插上也不会有串口数据传输。因此本开发板实际使用中不要在系统工作的时候插拔USB串口！！！客户自己设计底板的时候可以根据实际使用场合，去掉这个隔离芯片

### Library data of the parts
3.3V 5V = Header 3X2: 3*2P接插件; 版权归属: 源创客
BAT = CR-3V: 微型电池; 版权归属: 正点原子
C1 = C: 50V 10% 无极性贴片电容; BOM名称: 电容; 版权归属: 正点原子
C2 = C: 无极性贴片电容; 版权归属: 正点原子
C3 C13 C26 C38 C39 = C-CM: 贴片电解电容; 版权归属: 源创客
C4 C5 C7 C12 C20 C21 C24 C25 C27-C37 C40-C45 C254-C256 = C: 无极性贴片电容; 版权归属: 源创客
D1-D3 = SMBJ: TVS
DC12V = P-DC: 低压电源接口; BOM名称: DC电源接口; 版权归属: 源创客
DZ1 DZ2 = BZT52BxVx: CJ x.xV / 0.5W稳压管  2%; 版权归属: 正点原子; BOM名称: 二极管(稳压)
F1 = FU: 贴片保险丝; 版权归属: 源创客
JP3 = Header 2X2: 2*2P接插件; 版权归属: 源创客
L1 = L: 小功率贴片电感磁珠; 版权归属: 正点原子
L2-L5 = L-CDRH: 功率屏蔽电感; 版权归属: 源创客
MOS1 = HSBB6115: PMOS -60V -8A@-4.5V 33mΩ; BOM名称: MOS管; 版权归属: 正点原子
PWR = LED-SMD: 贴片LED; 版权归属: 源创客
Q1 = 9015-SMD: 低噪放大-PNP型; BOM名称: 三极管; 版权归属: 正点原子; 属性: 50V 0.1A 0.4W 150MHZ
R5-R8 = R: 贴片电阻; BOM名称: 电阻; 版权归属: 正点原子
R9 R14 R18 R19 R25 R27-R30 R33-R38 R101 = R: 贴片电阻; 版权归属: 源创客
R44 R81 = R: 贴片电阻; 版权归属: 正点原子
S1 = SSW-1P: 1路波动开关; BOM名称: 波动开关; 版权归属: 源创客
U2 U3 U6 U7 = DC JW5060T_6: DC降压芯片
U4 = XC6206: LDO 5.5V 200-300mA; 版权归属: 正点原子; Parameter: 芯片
UART = USB Type-C: 12P TypeC 母座; 版权归属: 正点原子; Parameter: 接口器件
VD43 VD44 = ESD5341N: ESD二极管-单向

## Sheet 04_ATK_RV1126B_4G_USBHUB.SchDoc
size A4; Author: ALIENTEK; Revision: 0; SheetNumber: 4; SheetTotal: 13; Version: V1.0; SheetSize: A4
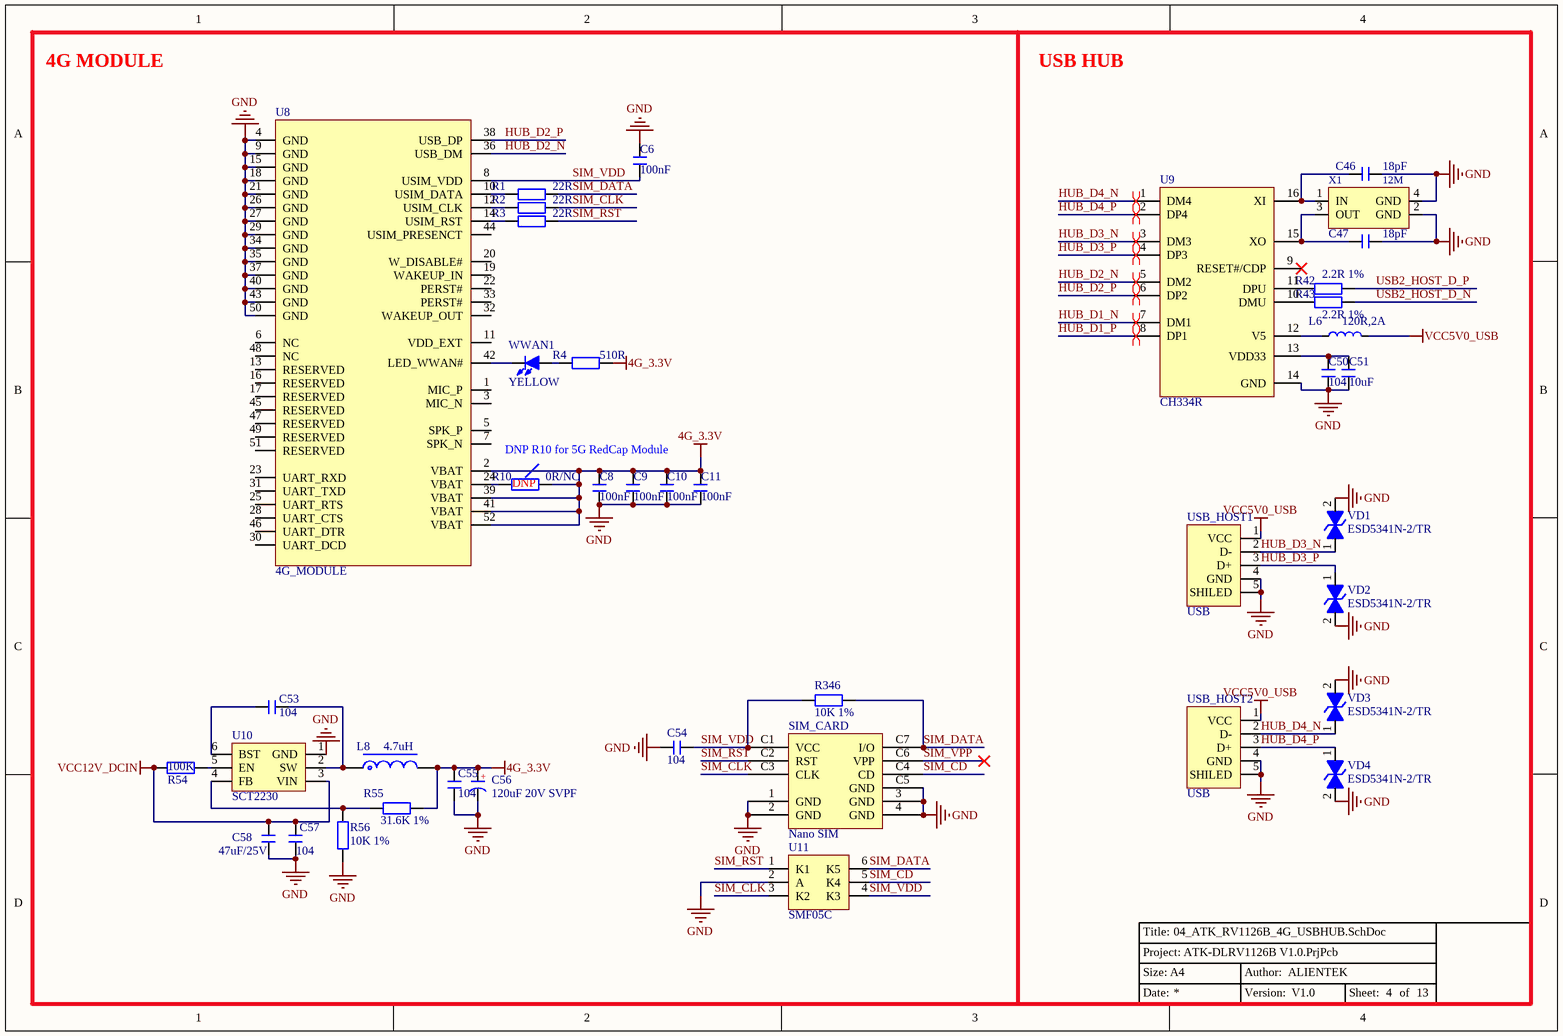
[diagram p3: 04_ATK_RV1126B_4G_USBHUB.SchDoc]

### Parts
C6  100nF  [C 0402]
C8  100nF  [C 0402]
C9  100nF  [C 0402]
C10  100nF  [C 0402]
C11  100nF  [C 0402]
C46  18pF  [C 0402]
C47  18pF  [C 0402]
C50  104  [C 0402]
C51  10uF  [C 0603]
C53  104  [C 0402]
C54  104  [C 0402]
C55  104  [C 0402]
C56  120uF 20V SVPF  [CM D(6.3*7.7)]
C57  104  [C 0402]
C58  47uF/25V  [C 1206]
L6  120R,2A  [L 0603]
L8  4.7uH  [L-SMD-0420]
R1  22R  [R 0402]
R2  22R  [R 0402]
R3  22R  [R 0402]
R4  510R  [R 0402]
R10  0R/NC  [R 0402]
R42  2.2R 1%  [R 0402]
R43  2.2R 1%  [R 0402]
R54  100K  [R 0402]
R55  31.6K 1%  [R 0402]
R56  10K 1%  [R 0402]
R346  10K 1%  [R 0402]
SIM_CARD  Nano SIM  [Nano SIM 7P]
U8  4G_MODULE  [Mini PCIE 52P]
U9  CH334R  [QSOP16]
U10  SCT2230  [SOT23-6N]
U11  SMF05C  [SOT363-6L]
USB_HOST1  USB  [USB-A/S_E]
USB_HOST2  USB  [USB-A/S_E]
VD1  ESD5341N-2/TR  [ESD0402]
VD2  ESD5341N-2/TR  [ESD0402]
VD3  ESD5341N-2/TR  [ESD0402]
VD4  ESD5341N-2/TR  [ESD0402]
WWAN1  YELLOW  [LED 0805G]
X1  12M  [XTAL-3225]

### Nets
4G_3.3V: C8.1 C9.1 C10.1 C11.1 C55.1 C56.1(A) L8.2 R4.1 R10.1 R55.2 U8.2(VBAT) U8.39(VBAT) U8.41(VBAT) U8.52(VBAT)
GND: C6.1 C8.2 C9.2 C10.2 C11.2 C46.2 C47.2 C50.1 C51.2 C54.2 C55.2 C56.2(K) C57.1 C58.1 R56.2 SIM_CARD.1(GND) SIM_CARD.2(GND) SIM_CARD.3(GND) SIM_CARD.4(GND) SIM_CARD.C5(GND) U8.4(GND) U8.9(GND) U8.15(GND) U8.18(GND) U8.21(GND) U8.26(GND) U8.27(GND) U8.29(GND) U8.34(GND) U8.35(GND) U8.37(GND) U8.40(GND) U8.43(GND) U8.50(GND) U9.14(GND) U10.1(GND) U11.2(A) USB_HOST1.4(GND) USB_HOST1.5(SHILED) USB_HOST2.4(GND) USB_HOST2.5(SHILED) VD1.2 VD2.2 VD3.2 VD4.2 X1.2(GND) X1.4(GND)
VCC5V0_USB: L6.2 USB_HOST1.1(VCC) USB_HOST2.1(VCC)
VCC12V_DCIN: C57.2 C58.2 R54.1 U10.3(VIN)
HUB_D1_N: U9.7(DM1)
HUB_D1_P: U9.8(DP1)
HUB_D2_N: U8.36(USB_DM) U9.5(DM2)
HUB_D2_P: U8.38(USB_DP) U9.6(DP2)
HUB_D3_N: U9.3(DM3) USB_HOST1.2(D-) VD1.1
HUB_D3_P: U9.4(DP3) USB_HOST1.3(D+) VD2.1
HUB_D4_N: U9.1(DM4) USB_HOST2.2(D-) VD3.1
HUB_D4_P: U9.2(DP4) USB_HOST2.3(D+) VD4.1
SIM_CD: SIM_CARD.C4(NC) U11.5(K4)
SIM_CLK: R2.1 SIM_CARD.C3(CLK) U11.3(K2)
SIM_DATA: R1.1 R346.2 SIM_CARD.C7(I/O) U11.6(K5)
SIM_RST: R3.1 SIM_CARD.C2(RST) U11.1(K1)
SIM_VDD: C6.2 C54.1 R346.1 SIM_CARD.C1(VCC) U8.8(USIM_VDD) U11.4(K3)
SIM_VPP: SIM_CARD.C6(VPP)
USB2_HOST_D_N: R43.2
USB2_HOST_D_P: R42.2
NetC46_1: C46.1 U9.16(XI) X1.1(IN)
NetC47_1: C47.1 U9.15(XO) X1.3(OUT)
NetC50_2: C50.2 C51.1 U9.13(VDD33)
NetC53_1: C53.1 U10.6(BST)
NetC53_2: C53.2 L8.1 U10.2(SW)
NetL6_1: L6.1 U9.12(V5)
NetR1_2: R1.2 U8.10(USIM_DATA)
NetR2_2: R2.2 U8.12(USIM_CLK)
NetR3_2: R3.2 U8.14(USIM_RST)
NetR4_2: R4.2 WWAN1.1(A)
NetR10_2: R10.2 U8.24(VBAT)
NetR42_1: R42.1 U9.11(DPU)
NetR43_1: R43.1 U9.10(DMU)
NetR54_2: R54.2 U10.5(EN)
NetR55_1: R55.1 R56.1 U10.4(FB)
NetU8_42: U8.42(LED_WWAN#) WWAN1.2(K)

Not connected (* = marked no-connect by the designer): U8 1(MIC_P) 3(MIC_N) 5(SPK_P) 6(NC) 7(SPK_N) 11(VDD_EXT) 13(RESERVED) 16(RESERVED) 17(RESERVED) 19(WAKEUP_IN) 20(W_DISABLE#) 22(PERST#) 23(UART_RXD) 25(UART_RTS) 28(UART_CTS) 30(UART_DCD) 31(UART_TXD) 32(WAKEUP_OUT) 33(PERST#) 44(USIM_PRESENCT) 45(RESERVED) 46(UART_DTR) 47(RESERVED) 48(NC) 49(RESERVED) 51(RESERVED); U9 9(RESET#/CDP)*

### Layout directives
differential pair: HUB_D1_N, HUB_D1_P, HUB_D2_N, HUB_D2_P, HUB_D3_N, HUB_D3_P, HUB_D4_N, HUB_D4_P

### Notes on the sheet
- 4G MODULE
- USB HUB
- DNP R10 for 5G RedCap Module
- (near R10) DNP

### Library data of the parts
C6 C8-C11 = C: 无极性电容; BOM名称: 无极性贴片电容; 版权归属: 正点原子
C46 C47 C50 C51 C53-C55 C57 C58 = C: 无极性贴片电容; 版权归属: 源创客
C56 = C-CM: 贴片电解电容; 版权归属: 源创客
L6 = L: 小功率贴片电感磁珠; 版权归属: 正点原子
L8 = L-CDRH: 功率屏蔽电感; 版权归属: 源创客
R1-R4 R10 = R: 贴片电阻; BOM名称: 电阻; 版权归属: 正点原子
R42 R43 R54-R56 R346 = R: 贴片电阻; 版权归属: 源创客
U8 = 4G-EC20
U10 = DC JW5060T_6: DC降压芯片
USB_HOST1 USB_HOST2 = USB-A/S: USB-A型母接口; 版权归属: 正点原子; Parameter: 接口器件
VD1-VD4 = ESD5341N: ESD二极管-单向
WWAN1 = LED-SMD: 贴片LED; 版权归属: 正点原子
X1 = XTAL-4P: 4脚无源晶振; BOM名称: 4脚晶振; 版权归属: 源创客

## Sheet 05_ATK_RV1126B_DEVICE.SchDoc
size A4; Author: ALIENTEK; Revision: 0; SheetNumber: 5; SheetTotal: 13; Version: V1.0; SheetSize: A4
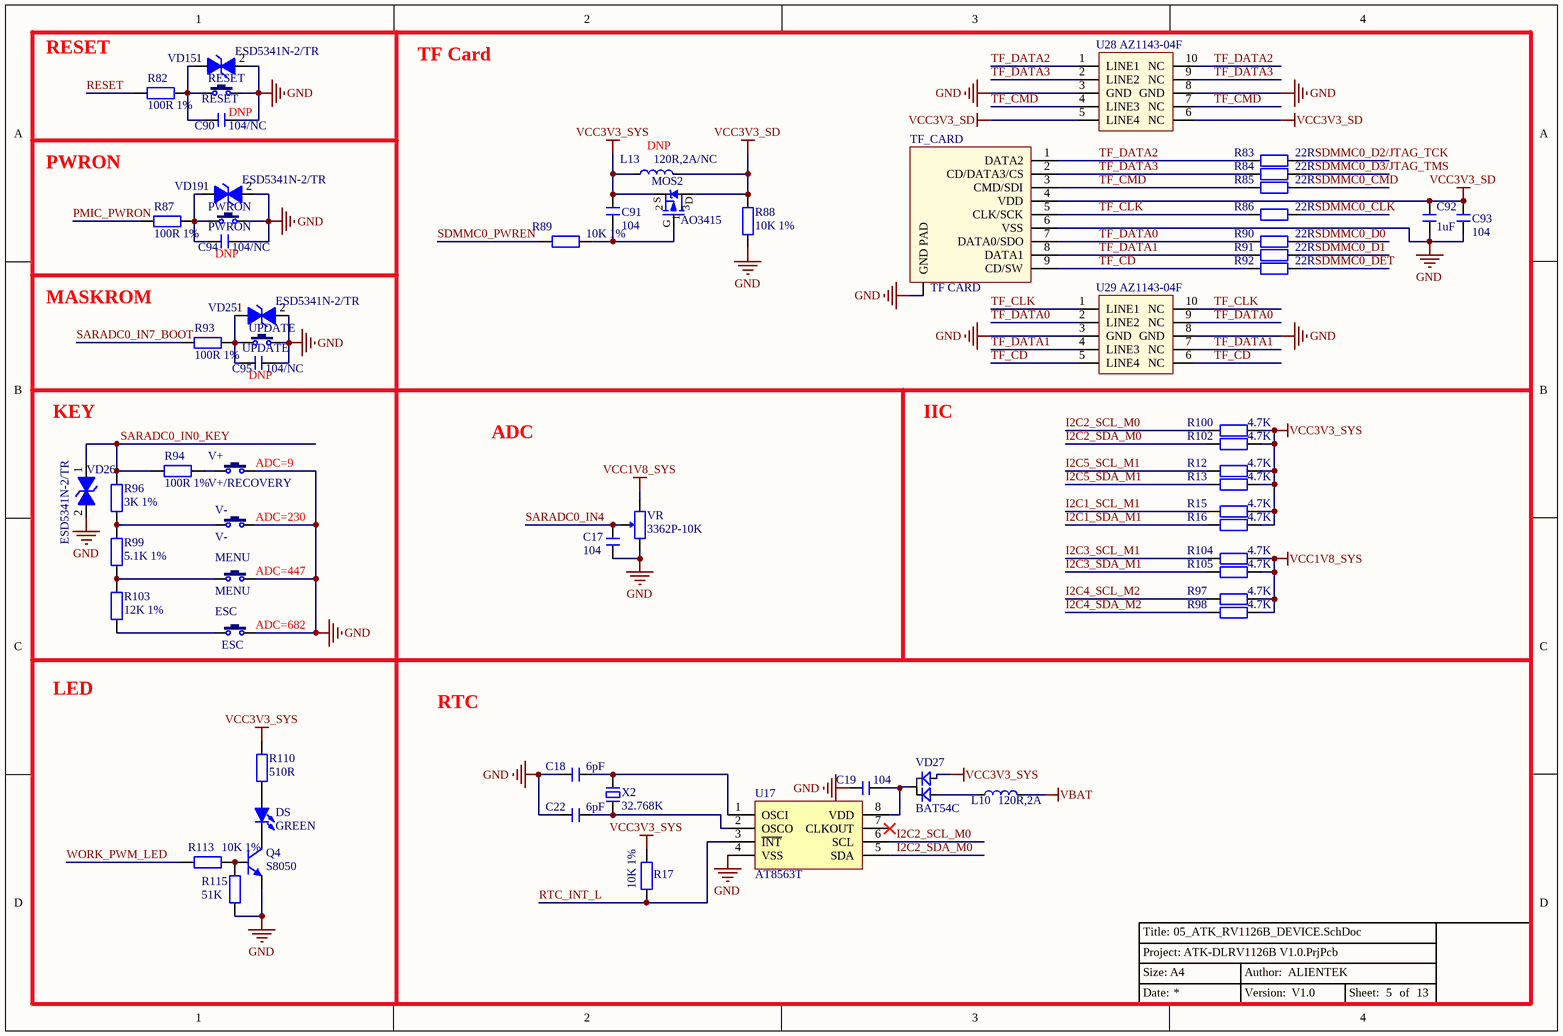
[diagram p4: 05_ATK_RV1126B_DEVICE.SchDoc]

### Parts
C17  104  [C 0402]
C18  6pF  [C 0402]
C19  104  [C 0402]
C22  6pF  [C 0402]
C90  104/NC  [C 0402]
C91  104  [C 0402]
C92  1uF  [C 0402]
C93  104  [C 0402]
C94  104/NC  [C 0402]
C95  104/NC  [C 0402]
DS  GREEN  [LED 0805G]
ESC  ESC  [KEY_SOP324225]
L10  120R,2A  [L 0603]
L13  120R,2A/NC  [L 0603]
MENU  MENU  [KEY_SOP324225]
MOS2  AO3415  [SOT23-3N]
PWRON  PWRON  [KEY_SOP324225]
Q4  S8050  [SOT23-3N]
R12  4.7K  [R 0402]
R13  4.7K  [R 0402]
R15  4.7K  [R 0402]
R16  4.7K  [R 0402]
R17  10K 1%  [R 0402]
R82  100R 1%  [R 0402]
R83  22R  [R 0402]
R84  22R  [R 0402]
R85  22R  [R 0402]
R86  22R  [R 0402]
R87  100R 1%  [R 0402]
R88  10K 1%  [R 0402]
R89  10K 1%  [R 0402]
R90  22R  [R 0402]
R91  22R  [R 0402]
R92  22R  [R 0402]
R93  100R 1%  [R 0402]
R94  100R 1%  [R 0402]
R96  3K 1%  [R 0402]
R97  4.7K  [R 0402]
R98  4.7K  [R 0402]
R99  5.1K 1%  [R 0402]
R100  4.7K  [R 0402]
R102  4.7K  [R 0402]
R103  12K 1%  [R 0402]
R104  4.7K  [R 0402]
R105  4.7K  [R 0402]
R110  510R  [R 0402]
R113  10K 1%  [R 0402]
R115  51K  [R 0402]
RESET  RESET  [KEY_SOP324225]
TF_CARD  TF CARD  [Micro SD]
U17  AT8563T  [SOP8_N]
U28  AZ1143-04F  [DFN2510P10E]
U29  AZ1143-04F  [DFN2510P10E]
UPDATE  UPDATE  [KEY_SOP324225]
V+  V+/RECOVERY  [KEY_SOP324225]
V-  V-  [KEY_SOP324225]
VD15  ESD5341N-2/TR  [ESD0402]
VD19  ESD5341N-2/TR  [ESD0402]
VD25  ESD5341N-2/TR  [ESD0402]
VD26  ESD5341N-2/TR  [ESD0402]
VD27  BAT54C  [SOT23-3N]
VR  3362P-10K  [3362P]
X2  32.768K  [XTAL-2X6H]

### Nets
GND: C17.1 C18.1 C19.1 C22.1 C90.2 C92.1 C93.2 C94.2 C95.2 ESC.2 MENU.2 PWRON.2 Q4.2(E) R88.1 R115.2 RESET.2 TF_CARD.0(GND_PAD) TF_CARD.6(VSS) U17.4(VSS) U28.3(GND) U28.8(GND) U29.3(GND) U29.8(GND) UPDATE.2 V+.2 V-.2 VD15.2 VD19.2 VD25.2 VD26.2 VR.1
VBAT: L10.2
VCC1V8_SYS: R97.1 R98.1 R104.1 R105.1 VR.3
VCC3V3_SD: C92.2 C93.1 L13.2 MOS2.3(D) R88.2 TF_CARD.4(VDD) U28.5(LINE4) U28.6(NC)
VCC3V3_SYS: C91.1 L13.1 MOS2.2(S) R12.1 R13.1 R15.1 R16.1 R17.1 R100.1 R102.1 R110.2 VD27.2
I2C1_SCL_M1: R15.2  [project net GPIO3_A2]
I2C1_SDA_M1: R16.2  [project net GPIO3_A3]
I2C2_SCL_M0: R100.2 U17.6(SCL)  [project net GPIO0_D0]
I2C2_SDA_M0: R102.2 U17.5(SDA)  [project net GPIO0_D1]
I2C3_SCL_M1: R104.2  [project net GPIO4_A4]
I2C3_SDA_M1: R105.2  [project net GPIO4_A5]
I2C4_SCL_M2: R97.2  [project net GPIO4_A7]
I2C4_SDA_M2: R98.2  [project net GPIO4_A6]
I2C5_SCL_M1: R12.2  [project net GPIO3_B6]
I2C5_SDA_M1: R13.2  [project net GPIO3_B7]
PMIC_PWRON: R87.1
RESET: R82.1
RTC_INT_L: R17.2 U17.3(~{INT})  [project net GPIO0_B1]
SARADC0_IN0_KEY: R94.2 R96.1 VD26.1
SARADC0_IN4: C17.2 VR.2
SARADC0_IN7_BOOT: R93.1
SDMMC0_CLK: R86.2  [project net GPIO2_A4]
SDMMC0_CMD: R85.2  [project net GPIO2_A5]
SDMMC0_D0: R90.2  [project net GPIO2_A0]
SDMMC0_D1: R91.2  [project net GPIO2_A1]
SDMMC0_D2/JTAG_TCK: R83.2  [project net GPIO2_A2]
SDMMC0_D3/JTAG_TMS: R84.2  [project net GPIO2_A3]
SDMMC0_DET: R92.2  [project net GPIO0_A5]
SDMMC0_PWREN: R89.1  [project net GPIO0_B0]
TF_CD: R92.1 TF_CARD.9(CD/SW) U29.5(LINE4) U29.6(NC)
TF_CLK: R86.1 TF_CARD.5(CLK/SCK) U29.1(LINE1) U29.10(NC)
TF_CMD: R85.1 TF_CARD.3(CMD/SDI) U28.4(LINE3) U28.7(NC)
TF_DATA0: R90.1 TF_CARD.7(DATA0/SDO) U29.2(LINE2) U29.9(NC)
TF_DATA1: R91.1 TF_CARD.8(DATA1) U29.4(LINE3) U29.7(NC)
TF_DATA2: R83.1 TF_CARD.1(DATA2) U28.1(LINE1) U28.10(NC)
TF_DATA3: R84.1 TF_CARD.2(CD/DATA3/CS) U28.2(LINE2) U28.9(NC)
WORK_PWM_LED: R113.2  [project net GPIO0_C5]
NetC18_2: C18.2 U17.1(OSCI) X2.1
NetC19_2: C19.2 U17.8(VDD) VD27.3
NetC22_2: C22.2 U17.2(OSCO) X2.2
NetC90_1: C90.1 R82.2 RESET.1 VD15.1
NetC91_2: C91.2 MOS2.1(G) R89.2
NetC94_1: C94.1 PWRON.1 R87.2 VD19.1
NetC95_1: C95.1 R93.2 UPDATE.1 VD25.1
NetDS_1: DS.1(A) R110.1
NetDS_2: DS.2(K) Q4.3(C)
NetESC_1: ESC.1 R103.2
NetL10_1: L10.1 VD27.1
NetMENU_1: MENU.1 R99.2 R103.1
NetQ4_1: Q4.1(B) R113.1 R115.1
NetR94_1: R94.1 V+.1
NetR96_2: R96.2 R99.1 V-.1

Not connected (* = marked no-connect by the designer): U17 7(CLKOUT)*

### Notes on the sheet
- RESET
- (near C90) DNP
- TF Card
- PWRON
- (near L13) DNP
- MASKROM
- (near C94) DNP
- (near C95) DNP
- KEY
- ADC
- IIC
- (near V+) ADC=9
- (near V-) ADC=230
- (near MENU) ADC=447
- (near ESC) ADC=682
- LED
- RTC

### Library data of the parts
C17-C19 C22 C90-C95 = C: 无极性贴片电容; 版权归属: 正点原子
DS = LED-SMD: 贴片LED; 版权归属: 正点原子; Parameter: 发光二极管
ESC MENU PWRON RESET UPDATE V+ V- = KEY: 按键; BOM名称: 3x6轻触开关; 版权归属: 正点原子
L10 L13 = L: 小功率贴片电感磁珠; 版权归属: 正点原子
MOS2 = AO3415: PMOS -20V-4.3A 45mΩ; BOM名称: P沟道场效应管; 版权归属: 正点原子; Parameter: MOS管
Q4 = 8050-SMD: 高频放大-NPN型; 版权归属: 正点原子; 属性: 40V 1.5A 1W 100MHZ; Parameter: 三极管
R12 R13 R15-R17 R82-R94 R96-R100 R102-R105 R110 R113 R115 = R: 贴片电阻; 版权归属: 正点原子
TF_CARD = Micro SD: Micro SD卡; 版权归属: 正点原子
U17 = PCF8563
U28 U29 = AZ1143-04F: ESD保护二极管阵列
VD15 VD19 VD25 VD26 = ESD5341N: ESD二极管-单向
VD27 = BAT54C: 肖特基二极管（双）
VR = RP-ID: 插件单联电位器; BOM名称: 插件电位器; 版权归属: 正点原子
X2 = XTAL-2P: 2脚无源晶振; BOM名称: 2脚晶振; 版权归属: 正点原子

## Sheet 06_ATK_RV1126B_ES8390_Audio.SchDoc
size A4; Author: ALIENTEK; Revision: 0; SheetNumber: 6; SheetTotal: 13; Version: V1.0; SheetSize: A4
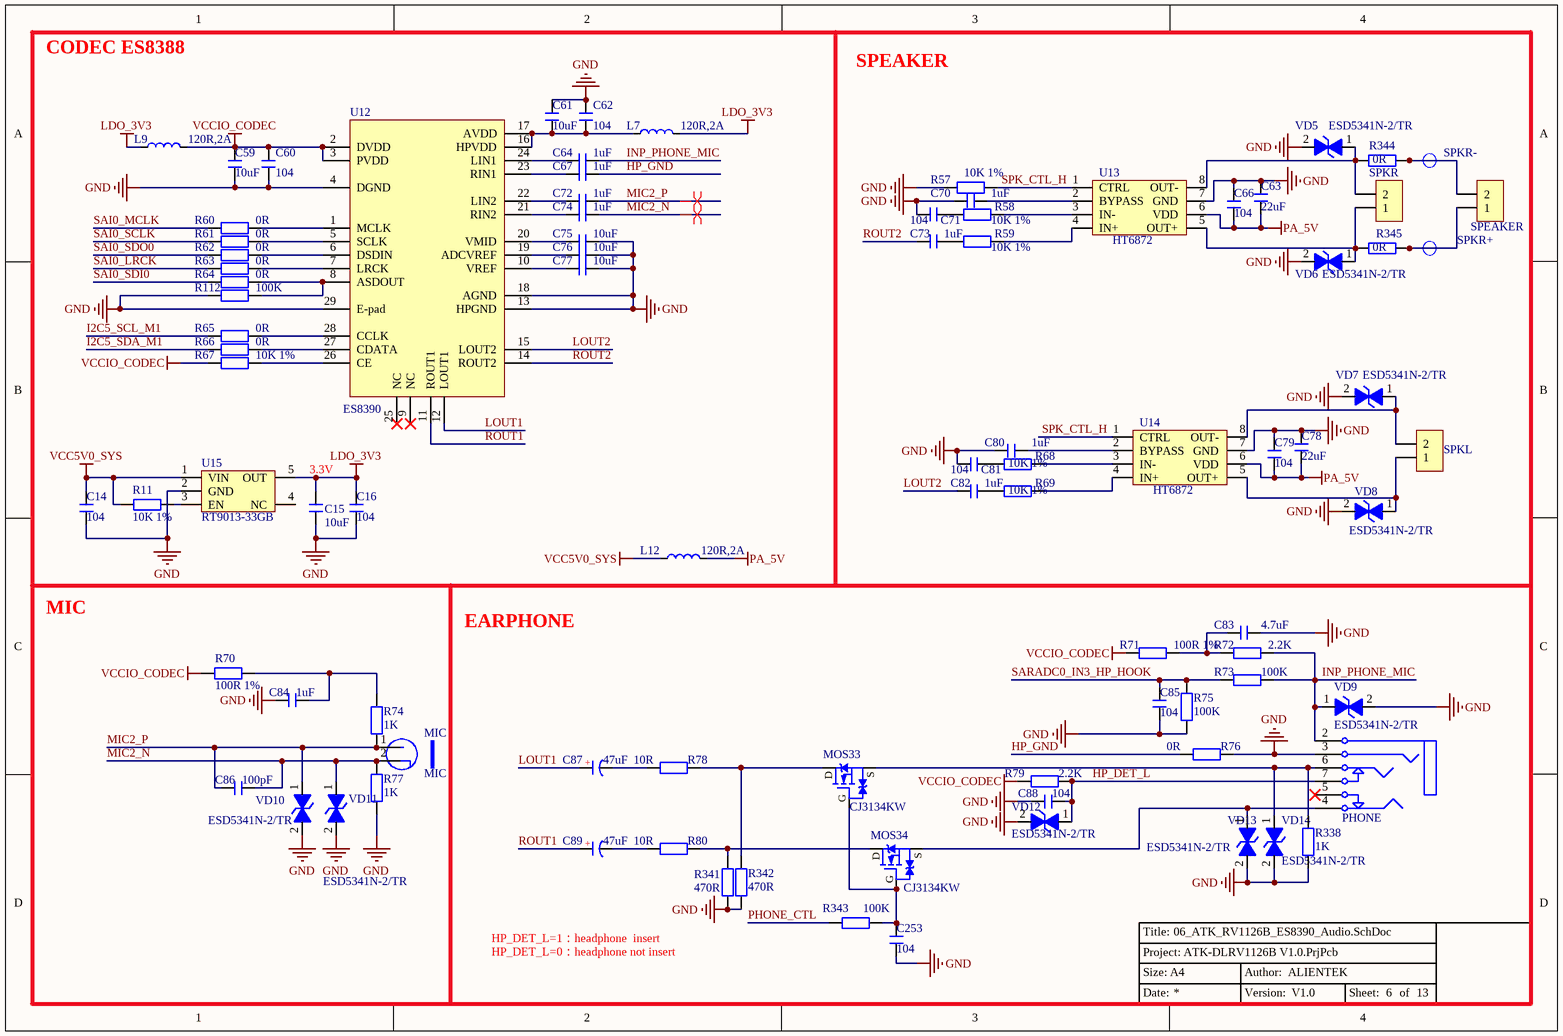
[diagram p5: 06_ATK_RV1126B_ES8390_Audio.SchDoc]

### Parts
(Parts that share a designator on the sheet are numbered #1, #2 ... from top to bottom, then left to right.)
C14  104  [C 0402]
C15  10uF  [C 0603]
C16  104  [C 0402]
C59  10uF  [C 0603]
C60  104  [C 0402]
C61  10uF  [C 0603]
C62  104  [C 0402]
C63  22uF  [C 0805]
C64  1uF  [C 0402]
C66  104  [C 0402]
C67  1uF  [C 0402]
C70  1uF  [C 0402]
C71  104  [C 0402]
C72  1uF  [C 0402]
C73  1uF  [C 0402]
C74  1uF  [C 0402]
C75  10uF  [C 0603]
C76  10uF  [C 0603]
C77  10uF  [C 0603]
C78  22uF  [C 0805]
C79  104  [C 0402]
C80  1uF  [C 0402]
C81  104  [C 0402]
C82  1uF  [C 0402]
C83  4.7uF  [C 0402]
C84  1uF  [C 0402]
C85  104  [C 0402]
C86  100pF  [C 0402]
C87  47uF  [CM B(4*5.4)]
C88  104  [C 0402]
C89  47uF  [CM B(4*5.4)]
C253  104  [C 0402]
L7  120R,2A  [L 0603]
L9  120R,2A  [L 0603]
L12  120R,2A  [L 0603]
MIC  MIC  [MIC-6022]
MOS33  CJ3134KW  [SOT323-3L]
MOS34  CJ3134KW  [SOT323-3L]
PHONE  PJ342  [PJ342A]  (value not drawn)
R11  10K 1%  [R 0402]
R57  10K 1%  [R 0402]
R58  10K 1%  [R 0402]
R59  10K 1%  [R 0402]
R60  0R  [R 0402]
R61  0R  [R 0402]
R62  0R  [R 0402]
R63  0R  [R 0402]
R64  0R  [R 0402]
R65  0R  [R 0402]
R66  0R  [R 0402]
R67  10K 1%  [R 0402]
R68  10K 1%  [R 0402]
R69  10K 1%  [R 0402]
R70  100R 1%  [R 0402]
R71  100R 1%  [R 0402]
R72  2.2K  [R 0402]
R73  100K  [R 0402]
R74  1K  [R 0402]
R75  100K  [R 0402]
R76  0R  [R 0402]
R77  1K  [R 0402]
R78  10R  [R 0402]
R79  2.2K  [R 0402]
R80  10R  [R 0402]
R112#1  100K  [R 0402]
R338  1K  [R 0402]
R341  470R  [R 0402]
R342  470R  [R 0402]
R343  100K  [R 0402]
R344  0R  [R 0402]
R345  0R  [R 0402]
SPEAKER  SPKL  [SPEAKER]  (value not drawn)
SPKL  SPKL  [XH2.54-2P_H]  (value not drawn)
SPKR  SPKL  [XH2.54-2P_H]  (value not drawn)
SPKR+  TP_0.7  [TEST 1]  (value not drawn)
SPKR-  TP_0.7  [TEST 1]  (value not drawn)
U12  ES8390  [QFN28 4X4_L]
U13  HT6872  [SOP8_N]
U14  HT6872  [SOP8_N]
U15  RT9013-33GB  [SOT23-5N]
VD5  ESD5341N-2/TR  [ESD0402]
VD6  ESD5341N-2/TR  [ESD0402]
VD7  ESD5341N-2/TR  [ESD0402]
VD8  ESD5341N-2/TR  [ESD0402]
VD9  ESD5341N-2/TR  [ESD0402]
VD10  ESD5341N-2/TR  [ESD0402]
VD11  ESD5341N-2/TR  [ESD0402]
VD12  ESD5341N-2/TR  [ESD0402]
VD13  ESD5341N-2/TR  [ESD0402]
VD14  ESD5341N-2/TR  [ESD0402]

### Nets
GND: C14.2 C15.1 C16.2 C59.2 C60.2 C61.1 C62.1 C63.1 C66.1 C70.2 C71.2 C75.2 C76.2 C77.2 C78.1 C79.1 C80.2 C81.2 C83.2 C84.2 C85.2 C88.2 C253.2 PHONE.3 R57.2 R75.1 R76.1 R77.2 R112#1.2 R338.2 R341.2 R342.2 U12.4(DGND) U12.13(HPGND) U12.18(AGND) U12.29(E-pad) U13.7(GND) U14.7(GND) U15.2(GND) VD5.2 VD6.2 VD7.2 VD8.2 VD9.2 VD10.2 VD11.2 VD12.2 VD13.2 VD14.2
LDO_3V3: C15.2 C16.1 L7.2 L9.1 U15.5(OUT)
PA_5V: C63.2 C66.2 C78.2 C79.2 L12.2 U13.6(VDD) U14.6(VDD)
VCC5V0_SYS: C14.1 L12.1 R11.1 U15.1(VIN)
VCCIO_CODEC: C59.1 C60.1 L9.2 R67.2 R70.2 R71.1 R79.1 U12.2(DVDD) U12.3(PVDD)
HP_DET_L: C88.1 PHONE.7 R79.2 VD12.1  [project net GPIO0_A4]
HP_GND: C67.2 R76.2
I2C5_SCL_M1: R65.2  [project net GPIO3_B6]
I2C5_SDA_M1: R66.2  [project net GPIO3_B7]
INP_PHONE_MIC: C64.2 PHONE.2 R72.2 R73.1 VD9.1
LOUT1: C87.1(A) U12.12(LOUT1)
LOUT2: C82.1 U12.15(LOUT2)
MIC2_N: C74.2 C86.1 MIC.2(GND) R77.1 VD11.1
MIC2_P: C72.2 C86.2 MIC.1(VCC) R74.2 VD10.1
PHONE_CTL: R343.1  [project net GPIO0_A2]
ROUT1: C89.1(A) U12.11(ROUT1)
ROUT2: C73.1 U12.14(ROUT2)
SAI0_LRCK: R63.2  [project net GPIO7_A3]
SAI0_MCLK: R60.2  [project net GPIO7_A2]
SAI0_SCLK: R61.2  [project net GPIO7_A0]
SAI0_SDI0: R64.2  [project net GPIO7_A6]
SAI0_SDO0: R62.2  [project net GPIO7_A5]
SARADC0_IN3_HP_HOOK: C85.1 R73.2 R75.2
SPK_CTL_H: R57.1 U13.1(CTRL) U14.1(CTRL)  [project net GPIO0_A0]
NetC61_2: C61.2 C62.2 L7.1 U12.16(HPVDD) U12.17(AVDD)
NetC64_1: C64.1 U12.24(LIN1)
NetC67_1: C67.1 U12.23(RIN1)
NetC70_1: C70.1 U13.2(BYPASS)
NetC71_1: C71.1 R58.2
NetC72_1: C72.1 U12.22(LIN2)
NetC73_2: C73.2 R59.1
NetC74_1: C74.1 U12.21(RIN2)
NetC75_1: C75.1 U12.20(VMID)
NetC76_1: C76.1 U12.19(ADCVREF)
NetC77_1: C77.1 U12.10(VREF)
NetC80_1: C80.1 U14.2(BYPASS)
NetC81_1: C81.1 R68.2
NetC82_2: C82.2 R69.1
NetC83_1: C83.1 R71.2 R72.1
NetC84_1: C84.1 R70.1 R74.1
NetC87_2: C87.2(K) R78.2
NetC89_2: C89.2(K) R80.2
NetC253_1: C253.1 MOS33.1(G) MOS34.1(G) R343.2
NetMOS33_2: MOS33.2(S) PHONE.6 R338.1 VD14.1
NetMOS33_3: MOS33.3(D) R78.1 R342.1
NetMOS34_2: MOS34.2(S) PHONE.4 VD13.1
NetMOS34_3: MOS34.3(D) R80.1 R341.1
NetR11_2: R11.2 U15.3(EN)
NetR58_1: R58.1 U13.3(IN-)
NetR59_2: R59.2 U13.4(IN+)
NetR60_1: R60.1 U12.1(MCLK)
NetR61_1: R61.1 U12.5(SCLK)
NetR62_1: R62.1 U12.6(DSDIN)
NetR63_1: R63.1 U12.7(LRCK)
NetR64_1: R64.1 R112#1.1 U12.8(ASDOUT)
NetR65_1: R65.1 U12.28(CCLK)
NetR66_1: R66.1 U12.27(CDATA)
NetR67_1: R67.1 U12.26(CE)
NetR68_1: R68.1 U14.3(IN-)
NetR69_2: R69.2 U14.4(IN+)
NetR344_1: R344.1 SPEAKER.2 SPKR-.1
NetR344_2: R344.2 SPKR.2 U13.8(OUT-) VD5.1
NetR345_1: R345.1 SPEAKER.1 SPKR+.1
NetR345_2: R345.2 SPKR.1 U13.5(OUT+) VD6.1
NetSPKL_1: SPKL.1 U14.5(OUT+) VD8.1
NetSPKL_2: SPKL.2 U14.8(OUT-) VD7.1

Not connected (* = marked no-connect by the designer): PHONE 5*; U12 9(NC)* 25(NC)*; U15 4(NC)

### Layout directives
differential pair: MIC2_N, MIC2_P

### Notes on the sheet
- CODEC ES8388
- SPEAKER
- 3.3V
- MIC
- EARPHONE
- HP_DET_L=1：headphone  insert
- HP_DET_L=0：headphone not insert

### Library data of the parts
C14 C16 C60 C62-C64 C66 C67 C70-C86 C88 C253 = C: 无极性贴片电容; 版权归属: 正点原子
C15 C59 C61 = C: 无极性贴片电容; 版权归属: 源创客
C87 C89 = C-CM: 贴片电解电容; 版权归属: 源创客
L7 L9 L12 = L: 小功率贴片电感磁珠; 版权归属: 正点原子
MOS33 MOS34 = 2SK3018: NMOS  30V 0.1A@2.5V 8Ω; BOM名称: N沟场效应管; 版权归属: 正点原子; Parameter: MOS管
PHONE = Phone-PJ3583: 3.5耳机插座,带检测和麦克风; BOM名称: 耳机插座; 版权归属: 正点原子; Parameter: 接口器件
R11 = R: 贴片电阻; BOM名称: 电阻; 版权归属: 正点原子
R57-R80 R112#1 R338 R341-R345 = R: 贴片电阻; 版权归属: 正点原子
SPEAKER SPKL SPKR = Header 2: 2P接插件; 版权归属: 源创客
SPKR+ SPKR- = TP: Test Point 0.7mm; Priority: A; RK PN: TESTPOINT_0R7
U12 = ES8388
U13 U14 = HT6871
U15 = RT9013: LDO 5.5V 500mA; BOM名称: 稳压芯片; 版权归属: 正点原子; Parameter: 芯片
VD5-VD14 = ESD5341N: ESD二极管-单向

## Sheet 07_ATK_RV1126B_Integrate_Audio_OPT.SchDoc
size A4; Author: ALIENTEK; Revision: 0; SheetNumber: 7; SheetTotal: 13; Version: V1.0; SheetSize: A4
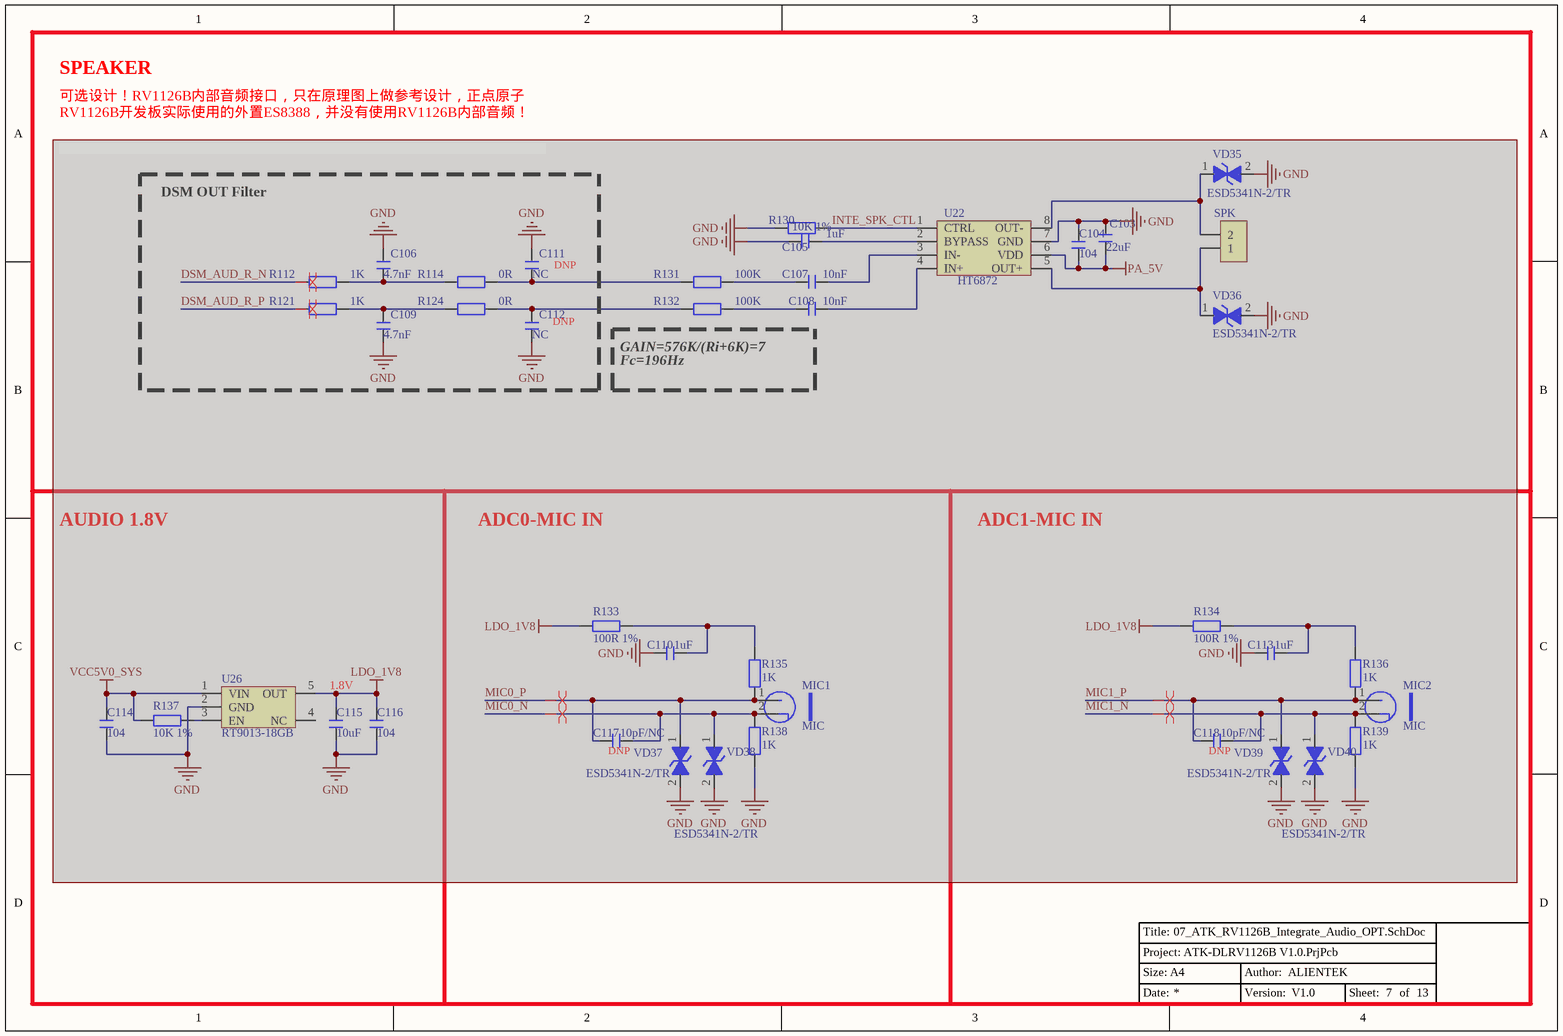
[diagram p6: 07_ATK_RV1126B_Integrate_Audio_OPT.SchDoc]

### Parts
(Parts that share a designator on the sheet are numbered #1, #2 ... from top to bottom, then left to right.)
C103  22uF  [C 0805]  (masked out: inside a compile mask, not in the netlist)
C104  104  [C 0402]  (masked out: inside a compile mask, not in the netlist)
C105  1uF  [C 0402]  (masked out: inside a compile mask, not in the netlist)
C106  4.7nF  [C 0402]  (masked out: inside a compile mask, not in the netlist)
C107  10nF  [C 0402]  (masked out: inside a compile mask, not in the netlist)
C108  10nF  [C 0402]  (masked out: inside a compile mask, not in the netlist)
C109  4.7nF  [C 0402]  (masked out: inside a compile mask, not in the netlist)
C110  1uF  [C 0402]  (masked out: inside a compile mask, not in the netlist)
C111  NC  [C 0402]  (masked out: inside a compile mask, not in the netlist)
C112  NC  [C 0402]  (masked out: inside a compile mask, not in the netlist)
C113  1uF  [C 0402]  (masked out: inside a compile mask, not in the netlist)
C114  104  [C 0402]  (masked out: inside a compile mask, not in the netlist)
C115  10uF  [C 0603]  (masked out: inside a compile mask, not in the netlist)
C116  104  [C 0402]  (masked out: inside a compile mask, not in the netlist)
C117  10pF/NC  [C 0402]  (masked out: inside a compile mask, not in the netlist)
C118  10pF/NC  [C 0402]  (masked out: inside a compile mask, not in the netlist)
MIC1  MIC  [MIC-6022]  (masked out: inside a compile mask, not in the netlist)
MIC2  MIC  [MIC-6022]  (masked out: inside a compile mask, not in the netlist)
R112#2  1K  [R 0402]  (masked out: inside a compile mask, not in the netlist)
R114  0R  [R 0402]  (masked out: inside a compile mask, not in the netlist)
R121  1K  [R 0402]  (masked out: inside a compile mask, not in the netlist)
R124  0R  [R 0402]  (masked out: inside a compile mask, not in the netlist)
R130  10K 1%  [R 0402]  (masked out: inside a compile mask, not in the netlist)
R131  100K  [R 0402]  (masked out: inside a compile mask, not in the netlist)
R132  100K  [R 0402]  (masked out: inside a compile mask, not in the netlist)
R133  100R 1%  [R 0402]  (masked out: inside a compile mask, not in the netlist)
R134  100R 1%  [R 0402]  (masked out: inside a compile mask, not in the netlist)
R135  1K  [R 0402]  (masked out: inside a compile mask, not in the netlist)
R136  1K  [R 0402]  (masked out: inside a compile mask, not in the netlist)
R137  10K 1%  [R 0402]  (masked out: inside a compile mask, not in the netlist)
R138  1K  [R 0402]  (masked out: inside a compile mask, not in the netlist)
R139  1K  [R 0402]  (masked out: inside a compile mask, not in the netlist)
SPK  SPKL  [XH2.54-2P_H]  (value not drawn)  (masked out: inside a compile mask, not in the netlist)
U22  HT6872  [SOP8_N]  (masked out: inside a compile mask, not in the netlist)
U26  RT9013-18GB  [SOT23-5N]  (masked out: inside a compile mask, not in the netlist)
VD35  ESD5341N-2/TR  [ESD0402]  (masked out: inside a compile mask, not in the netlist)
VD36  ESD5341N-2/TR  [ESD0402]  (masked out: inside a compile mask, not in the netlist)
VD37  ESD5341N-2/TR  [ESD0402]  (masked out: inside a compile mask, not in the netlist)
VD38  ESD5341N-2/TR  [ESD0402]  (masked out: inside a compile mask, not in the netlist)
VD39  ESD5341N-2/TR  [ESD0402]  (masked out: inside a compile mask, not in the netlist)
VD40  ESD5341N-2/TR  [ESD0402]  (masked out: inside a compile mask, not in the netlist)

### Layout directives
differential pair: (no net found under the mark)

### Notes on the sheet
- SPEAKER
- 可选设计！RV1126B内部音频接口，只在原理图上做参考设计，正点原子RV1126B开发板实际使用的外置ES8388，并没有使用RV1126B内部音频！
- DSM OUT Filter
- (near C111) DNP
- (near C112) DNP
- (near R132) GAIN=576K/(Ri+6K)=7
- Fc=196Hz
- AUDIO 1.8V
- ADC0-MIC IN
- ADC1-MIC IN
- 1.8V
- (near C117) DNP
- (near C118) DNP

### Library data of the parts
C103-C114 C116-C118 = C: 无极性贴片电容; 版权归属: 正点原子
C115 = C: 无极性贴片电容; 版权归属: 源创客
R112#2 R114 R121 R124 R130-R136 R138 R139 = R: 贴片电阻; 版权归属: 正点原子
R137 = R: 贴片电阻; BOM名称: 电阻; 版权归属: 正点原子
SPK = Header 2: 2P接插件; 版权归属: 源创客
U22 = HT6871
U26 = RT9013: as U15 on sheet 06_ATK_RV1126B_ES8390_Audio
VD35-VD40 = ESD5341N: ESD二极管-单向

## Sheet 08_ATK_RV1126B_RS485_CAN.SchDoc
size A4; Author: ALIENTEK; Revision: 0; SheetNumber: 8; SheetTotal: 13; Version: V1.0; SheetSize: A4
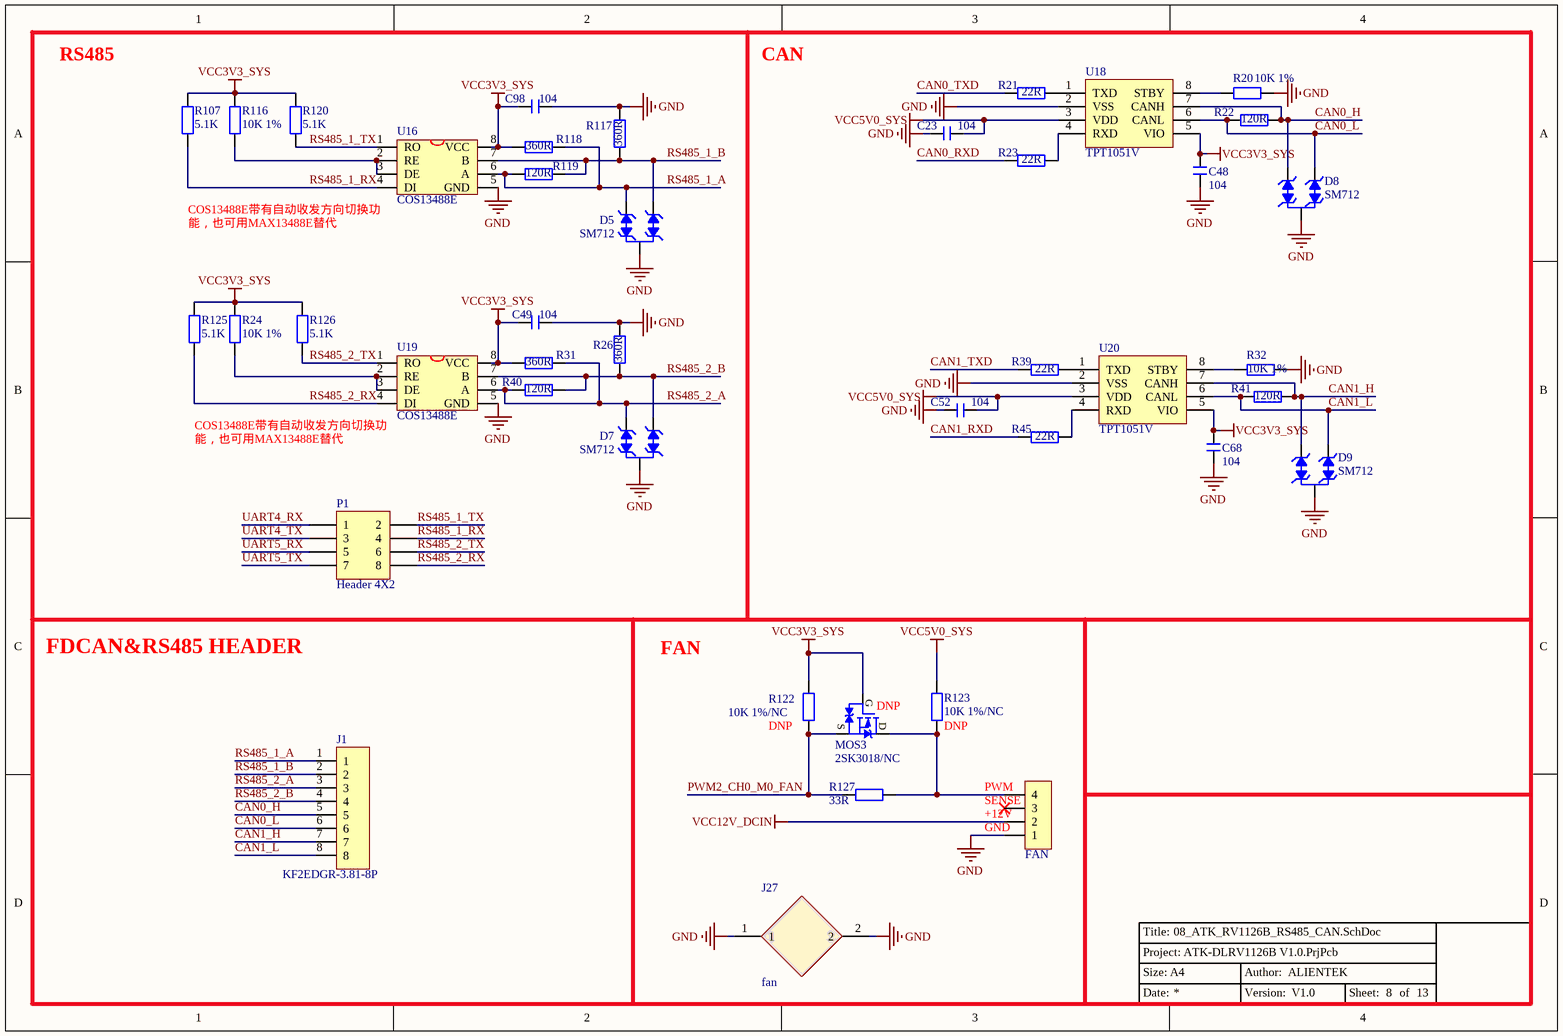
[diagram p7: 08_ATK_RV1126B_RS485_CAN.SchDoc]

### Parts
C23  104  [C 0402]
C48  104  [C 0402]
C49  104  [C 0402]
C52  104  [C 0402]
C68  104  [C 0402]
C98  104  [C 0402]
D5  SM712  [SOT23-3L]
D7  SM712  [SOT23-3L]
D8  SM712  [SOT23-3L]
D9  SM712  [SOT23-3L]
FAN  HDR-1X4  [PH2.0 D-L-4P]  (value not drawn)
J1  KF2EDGR-3.81-8P  [KF2EDGR_3.81_8P]
J27  fan  [40X40MM_FAN_59MM]
MOS3  2SK3018/NC  [SOT323-3L]
P1  Header 4X2  [HDR-4X2]
R20  10K 1%  [R 0402]
R21  22R  [R 0402]
R22  120R  [R 0402]
R23  22R  [R 0402]
R24  10K 1%  [R 0402]
R26  360R  [R 0402]
R31  360R  [R 0402]
R32  10K 1%  [R 0402]
R39  22R  [R 0402]
R40  120R  [R 0402]
R41  120R  [R 0402]
R45  22R  [R 0402]
R107  5.1K  [R 0402]
R116  10K 1%  [R 0402]
R117  360R  [R 0402]
R118  360R  [R 0402]
R119  120R  [R 0402]
R120  5.1K  [R 0402]
R122  10K 1%/NC  [R 0402]
R123  10K 1%/NC  [R 0402]
R125  5.1K  [R 0402]
R126  5.1K  [R 0402]
R127  33R  [R 0402]
U16  COS13488E  [SOP8_N]
U18  TPT1051V  [SOP8_N]
U19  COS13488E  [SOP8_N]
U20  TPT1051V  [SOP8_N]

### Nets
GND: C23.1 C48.2 C49.2 C52.1 C68.2 C98.2 D5.3 D7.3 D8.3 D9.3 FAN.1 J27.1 J27.2 R20.2 R26.1 R32.2 R117.1 U16.5(GND) U18.2(VSS) U19.5(GND) U20.2(VSS)
VCC3V3_SYS: C48.1 C49.1 C68.1 C98.1 MOS3.1(G) R24.2 R31.2 R107.1 R116.2 R118.2 R120.2 R122.2 R125.2 R126.2 U16.8(VCC) U18.5(VIO) U19.8(VCC) U20.5(VIO)
VCC5V0_SYS: C23.2 C52.2 R123.1 U18.3(VDD) U20.3(VDD)
VCC12V_DCIN: FAN.2
CAN0_H: D8.1 J1.5 R22.2 U18.7(CANH)
CAN0_L: D8.2 J1.6 R22.1 U18.6(CANL)
CAN0_RXD: R23.2
CAN0_TXD: R21.2
CAN1_H: D9.1 J1.7 R41.1 U20.7(CANH)
CAN1_L: D9.2 J1.8 R41.2 U20.6(CANL)
CAN1_RXD: R45.2
CAN1_TXD: R39.2
PWM2_CH0_M0_FAN: MOS3.2(S) R122.1 R127.2  [project net GPIO3_B2]
RS485_1_A: D5.2 J1.1 R118.1 R119.2 U16.6(A)
RS485_1_B: D5.1 J1.2 R117.2 R119.1 U16.7(B)
RS485_1_RX: P1.4 R107.2 U16.4(DI)
RS485_1_TX: P1.2 R120.1 U16.1(RO)
RS485_2_A: D7.2 J1.3 R31.1 R40.2 U19.6(A)
RS485_2_B: D7.1 J1.4 R26.2 R40.1 U19.7(B)
RS485_2_RX: P1.8 R125.1 U19.4(DI)
RS485_2_TX: P1.6 R126.1 U19.1(RO)
UART4_RX: P1.1  [project net GPIO5_A3]
UART4_TX: P1.3  [project net GMAC_PPSCLK]
UART5_RX: P1.5  [project net GPIO5_A5]
UART5_TX: P1.7  [project net GPIO5_A4]
NetFAN_4: FAN.4 MOS3.3(D) R123.2 R127.1
NetR20_1: R20.1 U18.8(STBY)
NetR21_1: R21.1 U18.1(TXD)
NetR23_1: R23.1 U18.4(RXD)
NetR24_1: R24.1 U19.2(RE) U19.3(DE)
NetR32_1: R32.1 U20.8(STBY)
NetR39_1: R39.1 U20.1(TXD)
NetR45_1: R45.1 U20.4(RXD)
NetR116_1: R116.1 U16.2(RE) U16.3(DE)

Not connected (* = marked no-connect by the designer): FAN 3*

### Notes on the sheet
- RS485
- CAN
- (near U16) COS13488E带有自动收发方向切换功能，也可用MAX13488E替代
- (near U19) COS13488E带有自动收发方向切换功能，也可用MAX13488E替代
- FDCAN&RS485 HEADER
- FAN
- (near MOS3) DNP
- (near R122) DNP
- (near R123) DNP
- (near FAN) PWM
- (near FAN) GND
- (near FAN) +12V
- (near FAN) SENSE

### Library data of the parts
C23 C48 C49 C52 C68 C98 = C: 无极性贴片电容; 版权归属: 正点原子
D5 D7-D9 = HDW24M2T-B: ESD
FAN = Header 4: 4P接插件; 版权归属: 正点原子; Parameter: 接插件
J1 = KF2EDGR-3.81-8P: 接线端子,8脚,间距3.81mm
MOS3 = 2SK3018: as MOS33 on sheet 06_ATK_RV1126B_ES8390_Audio
P1 = Header 4X2: Header, 4-Pin, Dual row
R20-R24 R26 R31 R32 R39-R41 R45 R116-R119 R122 R123 R127 = R: 贴片电阻; 版权归属: 正点原子
R107 R120 R125 R126 = R: 贴片电阻; BOM名称: 电阻; 版权归属: 正点原子
U16 U19 = MAX3485
U18 U20 = MCP2562FDT

## Sheet 09_ATK_RV1126B_RGMII_NET.SchDoc
size A4; Author: ALIENTEK; Revision: 0; SheetNumber: 9; SheetTotal: 13; Version: V1.0; SheetSize: A4
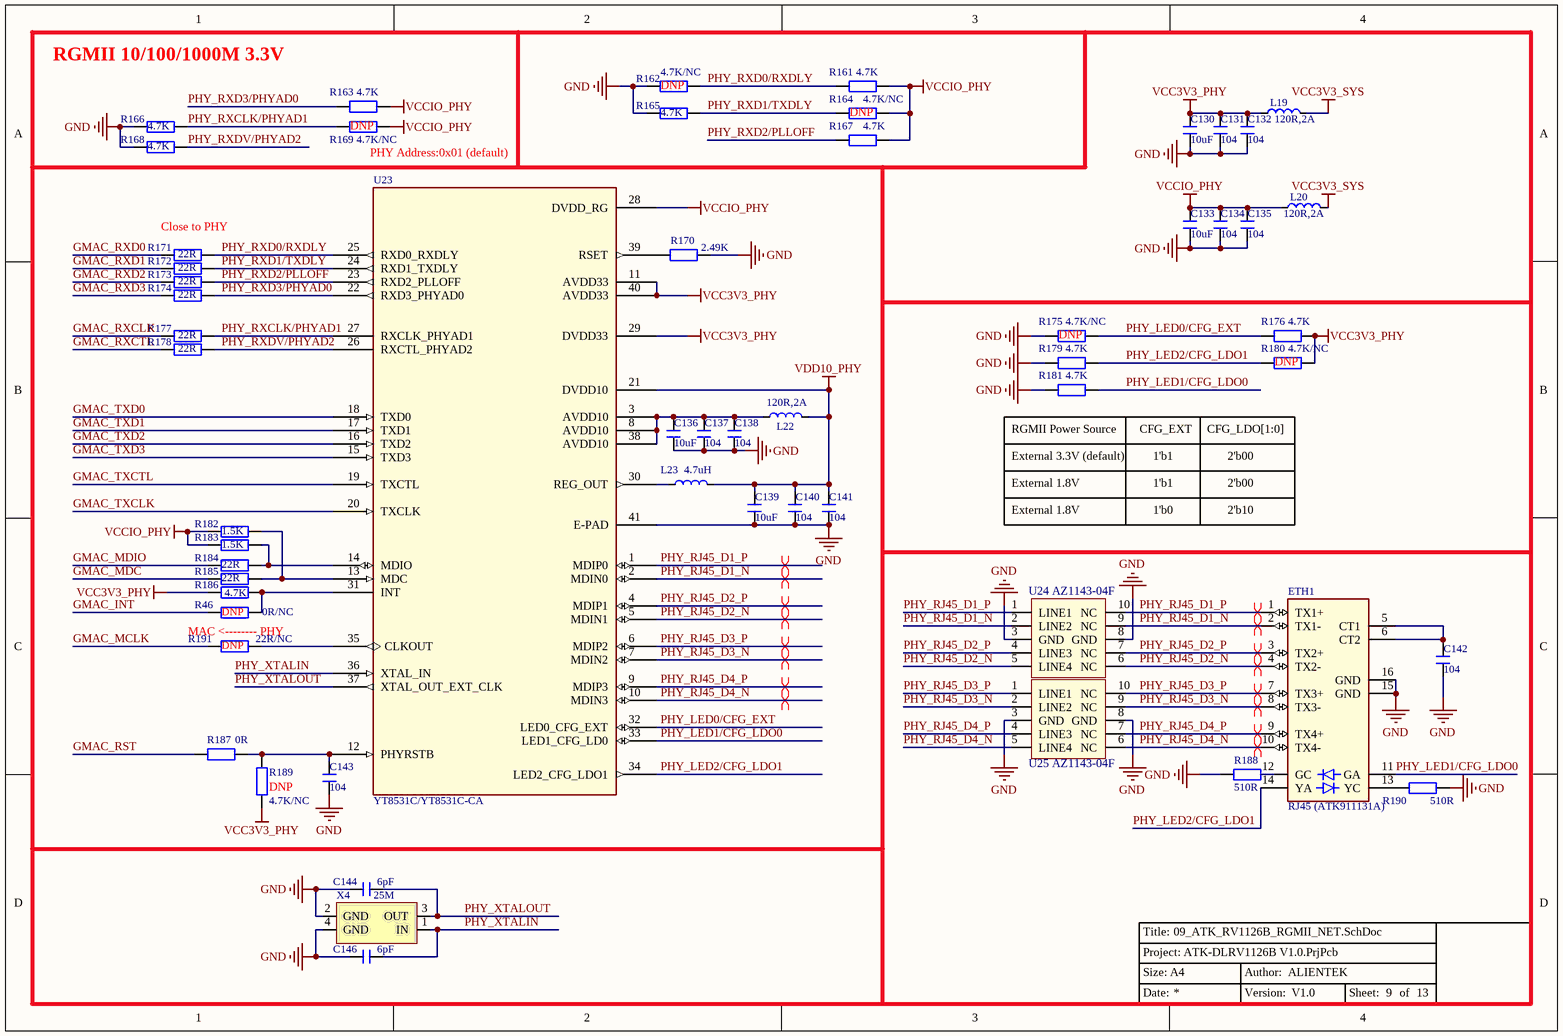
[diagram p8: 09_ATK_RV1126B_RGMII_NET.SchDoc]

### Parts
C130  10uF  [C 0603]
C131  104  [C 0402]
C132  104  [C 0402]
C133  10uF  [C 0603]
C134  104  [C 0402]
C135  104  [C 0402]
C136  10uF  [C 0603]
C137  104  [C 0402]
C138  104  [C 0402]
C139  10uF  [C 0603]
C140  104  [C 0402]
C141  104  [C 0402]
C142  104  [C 0402]
C143  104  [C 0402]
C144  6pF  [C 0402]
C146  6pF  [C 0402]
ETH1  RJ45 (ATK911131A)  [HR911131A]
L19  120R,2A  [L 0603]
L20  120R,2A  [L 0603]
L22  120R,2A  [L 0603]
L23  4.7uH  [L_2520]
R46  0R/NC  [R 0402]
R161  4.7K  [R 0402]
R162  4.7K/NC  [R 0402]
R163  4.7K  [R 0402]
R164  4.7K/NC  [R 0402]
R165  4.7K  [R 0402]
R166  4.7K  [R 0402]
R167  4.7K  [R 0402]
R168  4.7K  [R 0402]
R169  4.7K/NC  [R 0402]
R170  2.49K  [R 0402]
R171  22R  [R 0402]
R172  22R  [R 0402]
R173  22R  [R 0402]
R174  22R  [R 0402]
R175  4.7K/NC  [R 0402]
R176  4.7K  [R 0402]
R177  22R  [R 0402]
R178  22R  [R 0402]
R179  4.7K  [R 0402]
R180  4.7K/NC  [R 0402]
R181  4.7K  [R 0402]
R182  1.5K  [R 0402]
R183  1.5K  [R 0402]
R184  22R  [R 0402]
R185  22R  [R 0402]
R186  4.7K  [R 0402]
R187  0R  [R 0402]
R188  510R  [R 0402]
R189  4.7K/NC  [R 0402]
R190  510R  [R 0402]
R191  22R/NC  [R 0402]
U23  YT8531C/YT8531C-CA  [QFN40]
U24  AZ1143-04F  [DFN2510P10E]
U25  AZ1143-04F  [DFN2510P10E]
X4  25M  [XTAL-3225]

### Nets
GND: C130.1 C131.1 C132.1 C133.1 C134.1 C135.1 C136.1 C137.1 C138.1 C139.1 C140.1 C141.1 C142.1 C143.1 C144.2 C146.2 ETH1.15(GND) ETH1.16(GND) R162.1 R165.1 R166.2 R168.2 R170.2 R175.1 R179.1 R181.1 R188.1 R190.2 U23.41(E-PAD) U24.3(GND) U24.8(GND) U25.3(GND) U25.8(GND) X4.2(GND) X4.4(GND)
VCC3V3_PHY: C130.2 C131.2 C132.2 L19.1 R176.2 R180.2 R186.1 R189.2 U23.11(AVDD33) U23.29(DVDD33) U23.40(AVDD33)
VCC3V3_SYS: L19.2 L20.2
VCCIO_PHY: C133.2 C134.2 C135.2 L20.1 R161.2 R163.2 R164.2 R167.2 R169.2 R182.1 R183.1 U23.28(DVDD_RG)
VDD10_PHY: C139.2 C140.2 C141.2 L22.2 L23.2 U23.21(DVDD10)
GMAC_INT: R46.1
GMAC_MCLK: R191.1
GMAC_MDC: R185.1
GMAC_MDIO: R184.1
GMAC_RST: R187.1
GMAC_RXCLK: R177.2
GMAC_RXCTL: R178.2
GMAC_RXD0: R171.2
GMAC_RXD1: R172.2
GMAC_RXD2: R173.2
GMAC_RXD3: R174.2
GMAC_TXCLK: U23.20(TXCLK)
GMAC_TXCTL: U23.19(TXCTL)
GMAC_TXD0: U23.18(TXD0)
GMAC_TXD1: U23.17(TXD1)
GMAC_TXD2: U23.16(TXD2)
GMAC_TXD3: U23.15(TXD3)
PHY_LED0/CFG_EXT: R175.2 R176.1 U23.32(LED0_CFG_EXT)
PHY_LED1/CFG_LDO0: ETH1.11(GA) R181.2 U23.33(LED1_CFG_LD0)
PHY_LED2/CFG_LDO1: ETH1.14(YA) R179.2 R180.1 U23.34(LED2_CFG_LDO1)
PHY_RJ45_D1_N: ETH1.2(TX1-) U23.2(MDIN0) U24.2(LINE2) U24.9(NC)
PHY_RJ45_D1_P: ETH1.1(TX1+) U23.1(MDIP0) U24.1(LINE1) U24.10(NC)
PHY_RJ45_D2_N: ETH1.4(TX2-) U23.5(MDIN1) U24.5(LINE4) U24.6(NC)
PHY_RJ45_D2_P: ETH1.3(TX2+) U23.4(MDIP1) U24.4(LINE3) U24.7(NC)
PHY_RJ45_D3_N: ETH1.8(TX3-) U23.7(MDIN2) U25.2(LINE2) U25.9(NC)
PHY_RJ45_D3_P: ETH1.7(TX3+) U23.6(MDIP2) U25.1(LINE1) U25.10(NC)
PHY_RJ45_D4_N: ETH1.10(TX4-) U23.10(MDIN3) U25.5(LINE4) U25.6(NC)
PHY_RJ45_D4_P: ETH1.9(TX4+) U23.9(MDIP3) U25.4(LINE3) U25.7(NC)
PHY_RXCLK/PHYAD1: R166.1 R169.1 R177.1 U23.27(RXCLK_PHYAD1)
PHY_RXD0/RXDLY: R161.1 R162.2 R171.1 U23.25(RXD0_RXDLY)
PHY_RXD1/TXDLY: R164.1 R165.2 R172.1 U23.24(RXD1_TXDLY)
PHY_RXD2/PLLOFF: R167.1 R173.1 U23.23(RXD2_PLLOFF)
PHY_RXD3/PHYAD0: R163.1 R174.1 U23.22(RXD3_PHYAD0)
PHY_RXDV/PHYAD2: R168.1 R178.1 U23.26(RXCTL_PHYAD2)
PHY_XTALIN: C146.1 U23.36(XTAL_IN) X4.1(IN)
PHY_XTALOUT: C144.1 U23.37(XTAL_OUT_EXT_CLK) X4.3(OUT)
NetC136_2: C136.2 C137.2 C138.2 L22.1 U23.3(AVDD10) U23.8(AVDD10) U23.38(AVDD10)
NetC142_2: C142.2 ETH1.5(CT1) ETH1.6(CT2)
NetC143_2: C143.2 R187.2 R189.1 U23.12(PHYRSTB)
NetETH1_12: ETH1.12(GC) R188.2
NetETH1_13: ETH1.13(YC) R190.1
NetL23_1: L23.1 U23.30(REG_OUT)
NetR46_2: R46.2 R186.2 U23.31(INT)
NetR170_1: R170.1 U23.39(RSET)
NetR182_2: R182.2 R185.2 U23.13(MDC)
NetR183_2: R183.2 R184.2 U23.14(MDIO)
NetR191_2: R191.2 U23.35(CLKOUT)

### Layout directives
differential pair: PHY_RJ45_D1_N, PHY_RJ45_D1_P, PHY_RJ45_D2_N, PHY_RJ45_D2_P, PHY_RJ45_D3_N, PHY_RJ45_D3_P, PHY_RJ45_D4_N, PHY_RJ45_D4_P

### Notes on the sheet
- RGMII 10/100/1000M 3.3V
- (near R162) DNP
- (near R164) DNP
- (near R169) DNP
- (near R169) PHY Address:0x01 (default)
- Close to PHY
- (near R175) DNP
- (near R180) DNP
- (near R181) RGMII Power Source
- CFG_EXT
- CFG_LDO[1:0]
- External 3.3V (default)
- External 1.8V
- 1'b1
- 1'b0
- 2'b00
- 2'b10
- MAC <-------- PHY
- (near R191) DNP
- (near R46) DNP
- (near R189) DNP

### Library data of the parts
C130-C144 C146 = C: 无极性贴片电容; 版权归属: 源创客
ETH1 = HR911131A/C: 千兆以太网接口
L19 L20 L22 L23 = L: 小功率贴片电感磁珠; 版权归属: 源创客
R46 R161-R191 = R: 贴片电阻; 版权归属: 源创客
U23 = RTL8211F-CG
U24 U25 = AZ1143-04F: ESD保护二极管阵列
X4 = XTAL-4P: 4脚无源晶振; BOM名称: 4脚晶振; 版权归属: 源创客

## Sheet 10_ATK_RV1126B_FEPHY_NET_OPT.SchDoc
size A4; Author: ALIENTEK; Revision: 0; SheetNumber: 10; SheetTotal: 13; Version: V1.0; SheetSize: A4
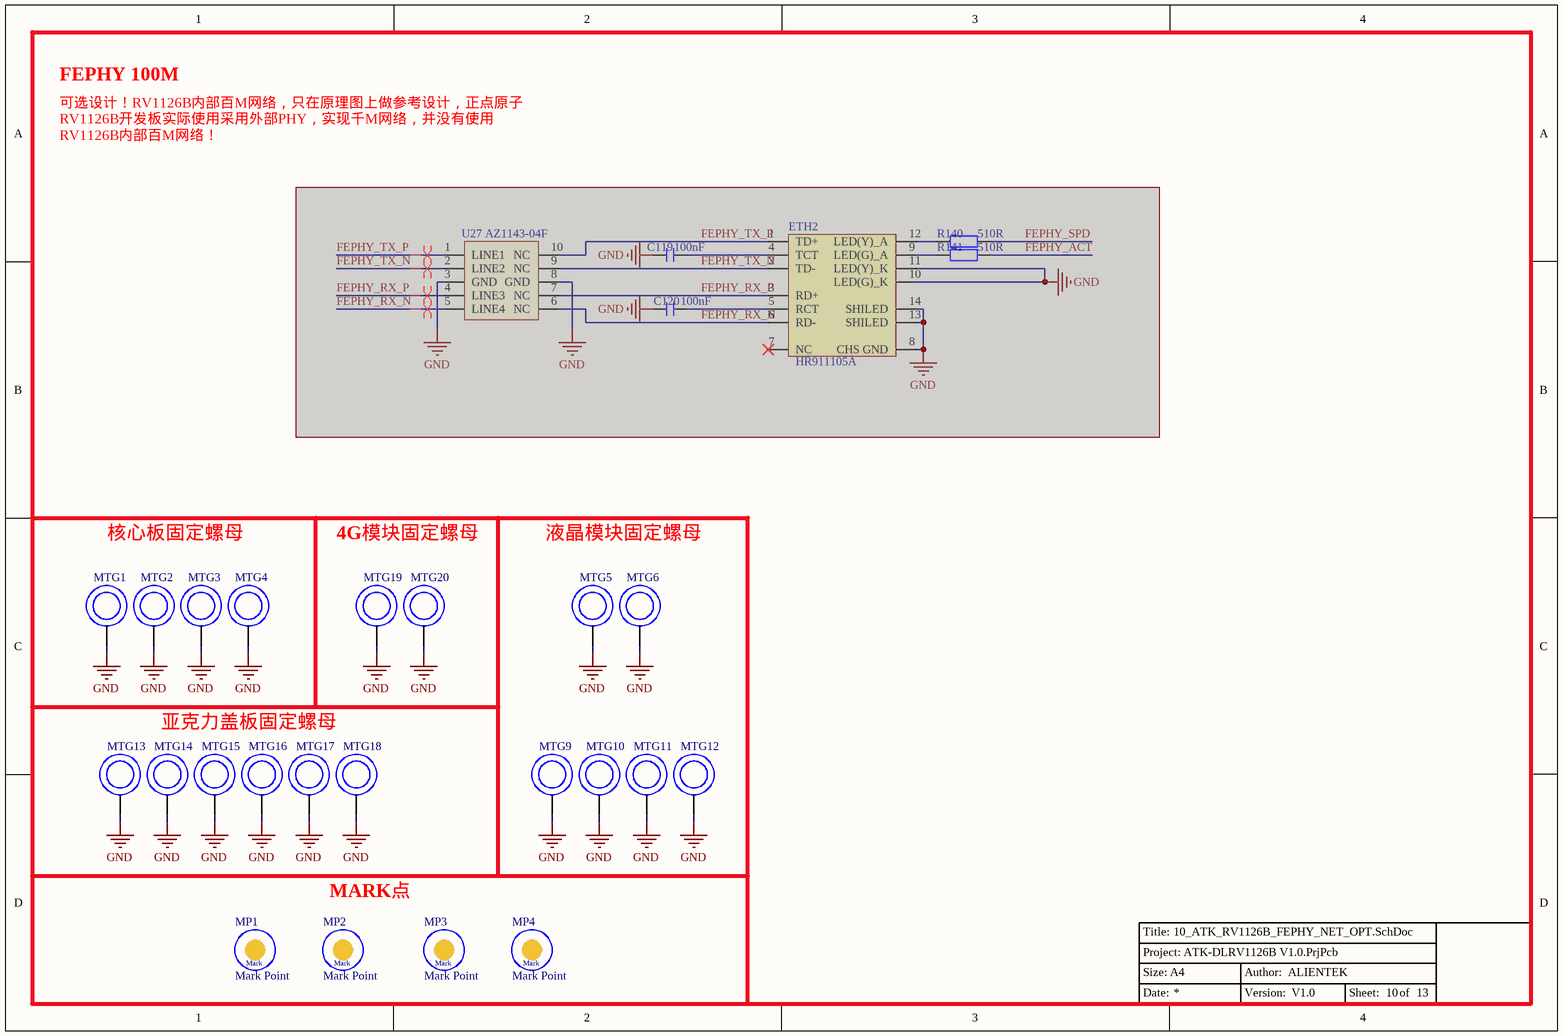
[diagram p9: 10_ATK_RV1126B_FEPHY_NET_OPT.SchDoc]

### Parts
C119  100nF  [C 0402]  (masked out: inside a compile mask, not in the netlist)
C120  100nF  [C 0402]  (masked out: inside a compile mask, not in the netlist)
ETH2  HR911105A  [HR911105A]  (masked out: inside a compile mask, not in the netlist)
MP1  Mark Point  [MARK POINT]
MP2  Mark Point  [MARK POINT]
MP3  Mark Point  [MARK POINT]
MP4  Mark Point  [MARK POINT]
MTG1  螺母(M2,贴片螺母柱,铜镀镍,M2x4x1.5+2.9x1.0)  [M2螺丝贴片螺母-直径4mm-高1.5mm]  (value not drawn)
MTG2  螺母(M2,贴片螺母柱,铜镀镍,M2x4x1.5+2.9x1.0)  [M2螺丝贴片螺母-直径4mm-高1.5mm]  (value not drawn)
MTG3  螺母(M2,贴片螺母柱,铜镀镍,M2x4x1.5+2.9x1.0)  [M2螺丝贴片螺母-直径4mm-高1.5mm]  (value not drawn)
MTG4  螺母(M2,贴片螺母柱,铜镀镍,M2x4x1.5+2.9x1.0)  [M2螺丝贴片螺母-直径4mm-高1.5mm]  (value not drawn)
MTG5  螺母(M3*6,贴片螺母柱,白色,SMTSO-M3-6ET)  [M3-6ET]  (value not drawn)
MTG6  螺母(M3*6,贴片螺母柱,白色,SMTSO-M3-6ET)  [M3-6ET]  (value not drawn)
MTG9  螺母(M3*6,贴片螺母柱,白色,SMTSO-M3-6ET)  [M3*23+6]  (value not drawn)
MTG10  螺母(M3*6,贴片螺母柱,白色,SMTSO-M3-6ET)  [M3*23+6]  (value not drawn)
MTG11  螺母(M3*6,贴片螺母柱,白色,SMTSO-M3-6ET)  [M3*23+6]  (value not drawn)
MTG12  螺母(M3*6,贴片螺母柱,白色,SMTSO-M3-6ET)  [M3*23+6]  (value not drawn)
MTG13  螺母(M3*6,贴片螺母柱,白色,SMTSO-M3-6ET)  [M3-6ET]  (value not drawn)
MTG14  螺母(M3*6,贴片螺母柱,白色,SMTSO-M3-6ET)  [M3-6ET]  (value not drawn)
MTG15  螺母(M3*6,贴片螺母柱,白色,SMTSO-M3-6ET)  [M3-6ET]  (value not drawn)
MTG16  螺母(M3*6,贴片螺母柱,白色,SMTSO-M3-6ET)  [M3-6ET]  (value not drawn)
MTG17  螺母(M3*6,贴片螺母柱,白色,SMTSO-M3-6ET)  [M3-6ET]  (value not drawn)
MTG18  螺母(M3*6,贴片螺母柱,白色,SMTSO-M3-6ET)  [M3-6ET]  (value not drawn)
MTG19  螺母(M3*6,贴片螺母柱,白色,SMTSO-M3-6ET)  [铜柱(M2.5,贴片铜柱,黄铜,2.9*2.2+4.0*4.3mm)]  (value not drawn)
MTG20  螺母(M3*6,贴片螺母柱,白色,SMTSO-M3-6ET)  [铜柱(M2.5,贴片铜柱,黄铜,2.9*2.2+4.0*4.3mm)]  (value not drawn)
R140  510R  [R 0402]  (masked out: inside a compile mask, not in the netlist)
R141  510R  [R 0402]  (masked out: inside a compile mask, not in the netlist)
U27  AZ1143-04F  [DFN2510P10E]  (masked out: inside a compile mask, not in the netlist)

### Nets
GND: MTG1.1 MTG2.1 MTG3.1 MTG4.1 MTG5.1 MTG6.1 MTG9.1 MTG10.1 MTG11.1 MTG12.1 MTG13.1 MTG14.1 MTG15.1 MTG16.1 MTG17.1 MTG18.1 MTG19.0 MTG20.0

Not connected (* = marked no-connect by the designer): MP1 1; MP2 1; MP3 1; MP4 1

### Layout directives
differential pair: (no net found under the mark)

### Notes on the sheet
- FEPHY 100M
- 可选设计！RV1126B内部百M网络，只在原理图上做参考设计，正点原子RV1126B开发板实际使用采用外部PHY，实现千M网络，并没有使用RV1126B内部百M网络！
- 核心板固定螺母
- 4G模块固定螺母
- 液晶模块固定螺母
- 亚克力盖板固定螺母
- (near MP2) MARK点

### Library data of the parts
C119 C120 = C: 无极性贴片电容; 版权归属: 源创客
ETH2 = HR911105
MP1-MP4 = MARK
MTG1-MTG4 = MTG_Hole: 301020006
MTG5 MTG6 MTG9-MTG20 = MTG_Hole: 301020001
R140 R141 = R: 贴片电阻; BOM名称: 电阻; 版权归属: 正点原子
U27 = AZ1143-04F: ESD保护二极管阵列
